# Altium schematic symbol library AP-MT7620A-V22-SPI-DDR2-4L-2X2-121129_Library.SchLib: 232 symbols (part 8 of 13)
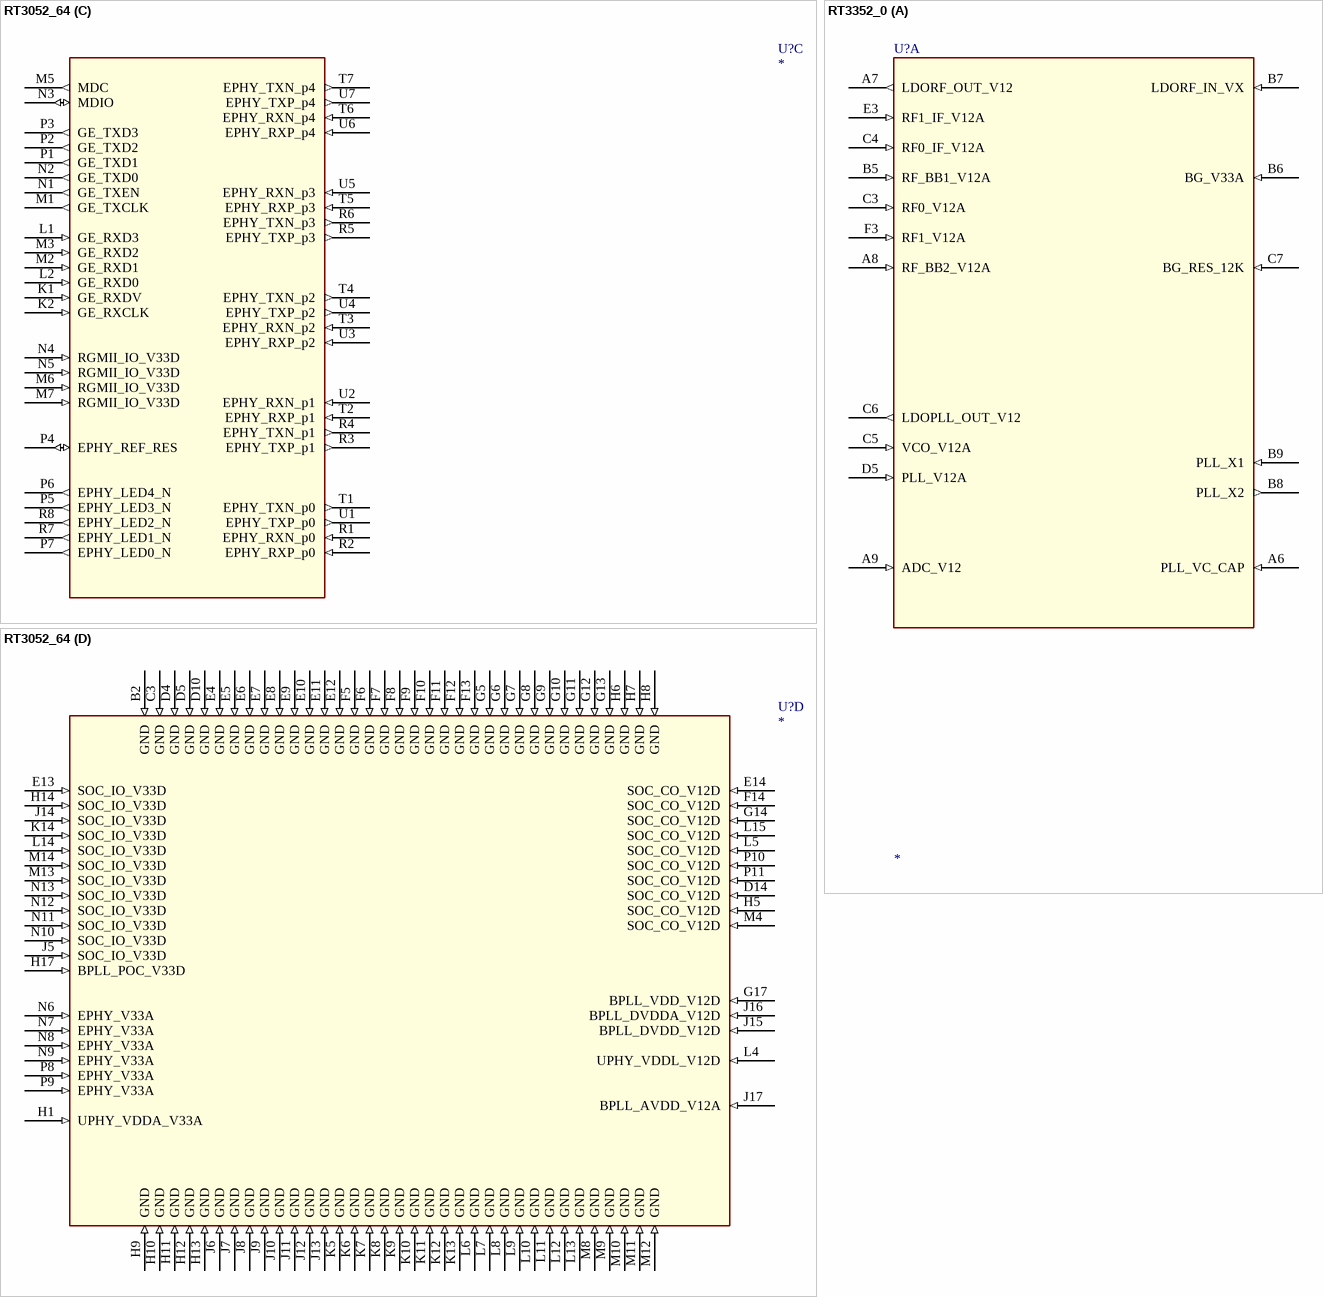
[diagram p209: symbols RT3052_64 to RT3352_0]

## RT3052_64
designator U?
footprint TFBGA289
part A pins: A1 RF0_V12A (in), A2 RF0_2G_OUT (out), A3 RF0_2G_INN (in), A4 RF0_2G_INP (in), A5 PLL_VC_CAP (in), A6 BG_RES_12K (in), A7 LDORF_OUT_V12 (out), A8 RF_BB2_V12A (in), A9 ADC_VREFN (in), A10 ADC_VREFP (in), A11 ADC_VREF025P (in), A12 ADC_VREF (in), A13 LDODIG_OUT_V12 (out), B1 RF1_2G_INP (in), B3 RF_BB1_V12A (in), B4 VCO_VCO_V12A (in), B5 PLL_DIV_V12A (in), B6 LDOPLL_OUT_V12 (out), B7 LDORF_IN_VX (in), B8 RF0_TSSI_IN (in), B9 ADC_V12A (in), B10 ADC_V12D (in), B11 ADC_VREF025N (in), B12 RF1_LNA_PE (out), C1 RF1_2G_INN (in), C2 RF1_V12A (in), C4 VCO_LO_V12A (in), C5 PLL_PRE_V12A (in), C6 PLL_X1 (io), C7 PLL_X2 (io), C8 BASE_TRX_IP (in), C9 BASE_TRX_QN (io), C10 RF0_LNA_PE (out), C11 LDOADC_IN_VX (in), C12 LDODIG_IN_VX (in), D1 RF1_2G_OUT (out), D2 RF0_PA_PE (out), D3 RF0_LO_V12A (in), D6 BG_V33A (in), D7 RF1_TSSI_IN (in), D8 BASE_TRX_IN (in), D9 BASE_TRX_QP (in), D11 LDOADC_OUT_V12 (in), D12 LDO_V33A (in), E1 RF1_PA_PE (out), E2 RF_V33A (in), E3 RF1_LO_V12A (in), F3 ANT_TRN (out), F4 WLAN_LED_N (out), G4 ANT_TRNB (out)
part B pins: A14 SRAM_CS_N (out), A15 MA20 (io), A16 MD1 (io), A17 MD6 (io), B13 OE_N (out), B14 FLASH_CS_N (out), B15 MD0 (io), B16 MD5 (io), B17 MD4 (io), C13 WE_N (out), C14 MA21 (io), C15 MD3 (io), C16 MD8 (io), C17 MD9 (io), D13 MA22 (io), D15 MD2 (io), D16 MD10 (io), D17 MD13 (io), E15 MD7 (io), E16 MD14 (io), E17 MD15 (io), F1 DSR_N (in), F2 TXD (out), F15 MD11 (io), F16 MA3 (io), F17 MA2 (io), G1 CTS_N (in), G2 RTS_N (out), G3 TXD2 (out), G15 MD12 (io), G16 MA1 (io), H2 UPHY_VRES (io), H3 DCD_N (in), H4 RXD2 (in), H15 MA4 (io), H16 MA0 (io), J1 UPHY_PADP (io), J2 UPHY_PADM (io), J3 RXD (in), J4 DTR_N (out), K3 UPHY_VBUS (io), K4 RIN (in), K15 MA5 (io), K16 MA7 (io), K17 MA6 (io), L3 UPHY_ID (io), L16 MA9 (io), L17 MA8 (io), M15 MA15 (io), M16 MA11 (io), M17 MA10 (io), N14 MD26 (io), N15 MA19 (io), N16 MA13 (io), N17 MA14 (io), P12 MD31 (io), P13 MD27 (io), P14 MD21 (io), P15 MD18 (io), P16 MA18 (io), P17 MA12 (io), R9 SPI_DIN (in), R10 I2C_SCLK (out), R11 JTAG_TDO (out), R12 MD25 (io), R13 MD30 (io), R14 MD22 (io), R15 MD19 (io), R16 SDRAM_CLK (out), R17 MA17 (io), T8 PORST_N (in), T9 SPI_CLK (out), T10 I2C_SD (io), T11 JTAG_TDI (in), T12 JTAG_TRST_N (in), T13 MD28 (io), T14 MD20 (io), T15 MD16 (io), T16 SDRAM_RAS_N (out), T17 MA16 (io), U8 SPI_DOUT (out), U9 SPI_EN (out), U10 GPIO0 (io), U11 JTAG_TMS (in), U12 JTAG_TCLK (in), U13 MD29 (io), U14 MD24 (io), U15 MD23 (io), U16 MD17 (io), U17 SDRAM_CS_N (out)
part C pins: K1 GE_RXDV (in), K2 GE_RXCLK (in), L1 GE_RXD3 (in), L2 GE_RXD0 (in), M1 GE_TXCLK (out), M2 GE_RXD1 (in), M3 GE_RXD2 (in), M5 MDC (out), M6 RGMII_IO_V33D (in), M7 RGMII_IO_V33D (in), N1 GE_TXEN (out), N2 GE_TXD0 (out), N3 MDIO (io), N4 RGMII_IO_V33D (in), N5 RGMII_IO_V33D (in), P1 GE_TXD1 (out), P2 GE_TXD2 (out), P3 GE_TXD3 (out), P4 EPHY_REF_RES (io), P5 EPHY_LED3_N (out), P6 EPHY_LED4_N (out), P7 EPHY_LED0_N (out), R1 EPHY_RXN_p0 (in), R2 EPHY_RXP_p0 (in), R3 EPHY_TXP_p1 (out), R4 EPHY_TXN_p1 (out), R5 EPHY_TXP_p3 (out), R6 EPHY_TXN_p3 (out), R7 EPHY_LED1_N (out), R8 EPHY_LED2_N (out), T1 EPHY_TXN_p0 (out), T2 EPHY_RXP_p1 (in), T3 EPHY_RXN_p2 (in), T4 EPHY_TXN_p2 (out), T5 EPHY_RXP_p3 (in), T6 EPHY_RXN_p4 (in), T7 EPHY_TXN_p4 (out), U1 EPHY_TXP_p0 (out), U2 EPHY_RXN_p1 (in), U3 EPHY_RXP_p2 (in), U4 EPHY_TXP_p2 (out), U5 EPHY_RXN_p3 (in), U6 EPHY_RXP_p4 (in), U7 EPHY_TXP_p4 (out)
part D pins: B2 GND (in), C3 GND (in), D4 GND (in), D5 GND (in), D10 GND (in), D14 SOC_CO_V12D (in), E4 GND (in), E5 GND (in), E6 GND (in), E7 GND (in), E8 GND (in), E9 GND (in), E10 GND (in), E11 GND (in), E12 GND (in), E13 SOC_IO_V33D (in), E14 SOC_CO_V12D (in), F5 GND (in), F6 GND (in), F7 GND (in), F8 GND (in), F9 GND (in), F10 GND (in), F11 GND (in), F12 GND (in), F13 GND (in), F14 SOC_CO_V12D (in), G5 GND (in), G6 GND (in), G7 GND (in), G8 GND (in), G9 GND (in), G10 GND (in), G11 GND (in), G12 GND (in), G13 GND (in), G14 SOC_CO_V12D (in), G17 BPLL_VDD_V12D (in), H1 UPHY_VDDA_V33A (in), H5 SOC_CO_V12D (in), H6 GND (in), H7 GND (in), H8 GND (in), H9 GND (in), H10 GND (in), H11 GND (in), H12 GND (in), H13 GND (in), H14 SOC_IO_V33D (in), H17 BPLL_POC_V33D (in), J5 SOC_IO_V33D (in), J6 GND (in), J7 GND (in), J8 GND (in), J9 GND (in), J10 GND (in), J11 GND (in), J12 GND (in), J13 GND (in), J14 SOC_IO_V33D (in), J15 BPLL_DVDD_V12D (in), J16 BPLL_DVDDA_V12D (in), J17 BPLL_AVDD_V12A (in), K5 GND (in), K6 GND (in), K7 GND (in), K8 GND (in), K9 GND (in), K10 GND (in), K11 GND (in), K12 GND (in), K13 GND (in), K14 SOC_IO_V33D (in), L4 UPHY_VDDL_V12D (in), L5 SOC_CO_V12D (in), L6 GND (in), L7 GND (in), L8 GND (in), L9 GND (in), L10 GND (in), L11 GND (in), L12 GND (in), L13 GND (in), L14 SOC_IO_V33D (in), L15 SOC_CO_V12D (in), M4 SOC_CO_V12D (in), M8 GND (in), M9 GND (in), M10 GND (in), M11 GND (in), M12 GND (in), M13 SOC_IO_V33D (in), M14 SOC_IO_V33D (in), N6 EPHY_V33A (in), N7 EPHY_V33A (in), N8 EPHY_V33A (in), N9 EPHY_V33A (in), N10 SOC_IO_V33D (in), N11 SOC_IO_V33D (in), N12 SOC_IO_V33D (in), N13 SOC_IO_V33D (in), P8 EPHY_V33A (in), P9 EPHY_V33A (in), P10 SOC_CO_V12D (in), P11 SOC_CO_V12D (in)

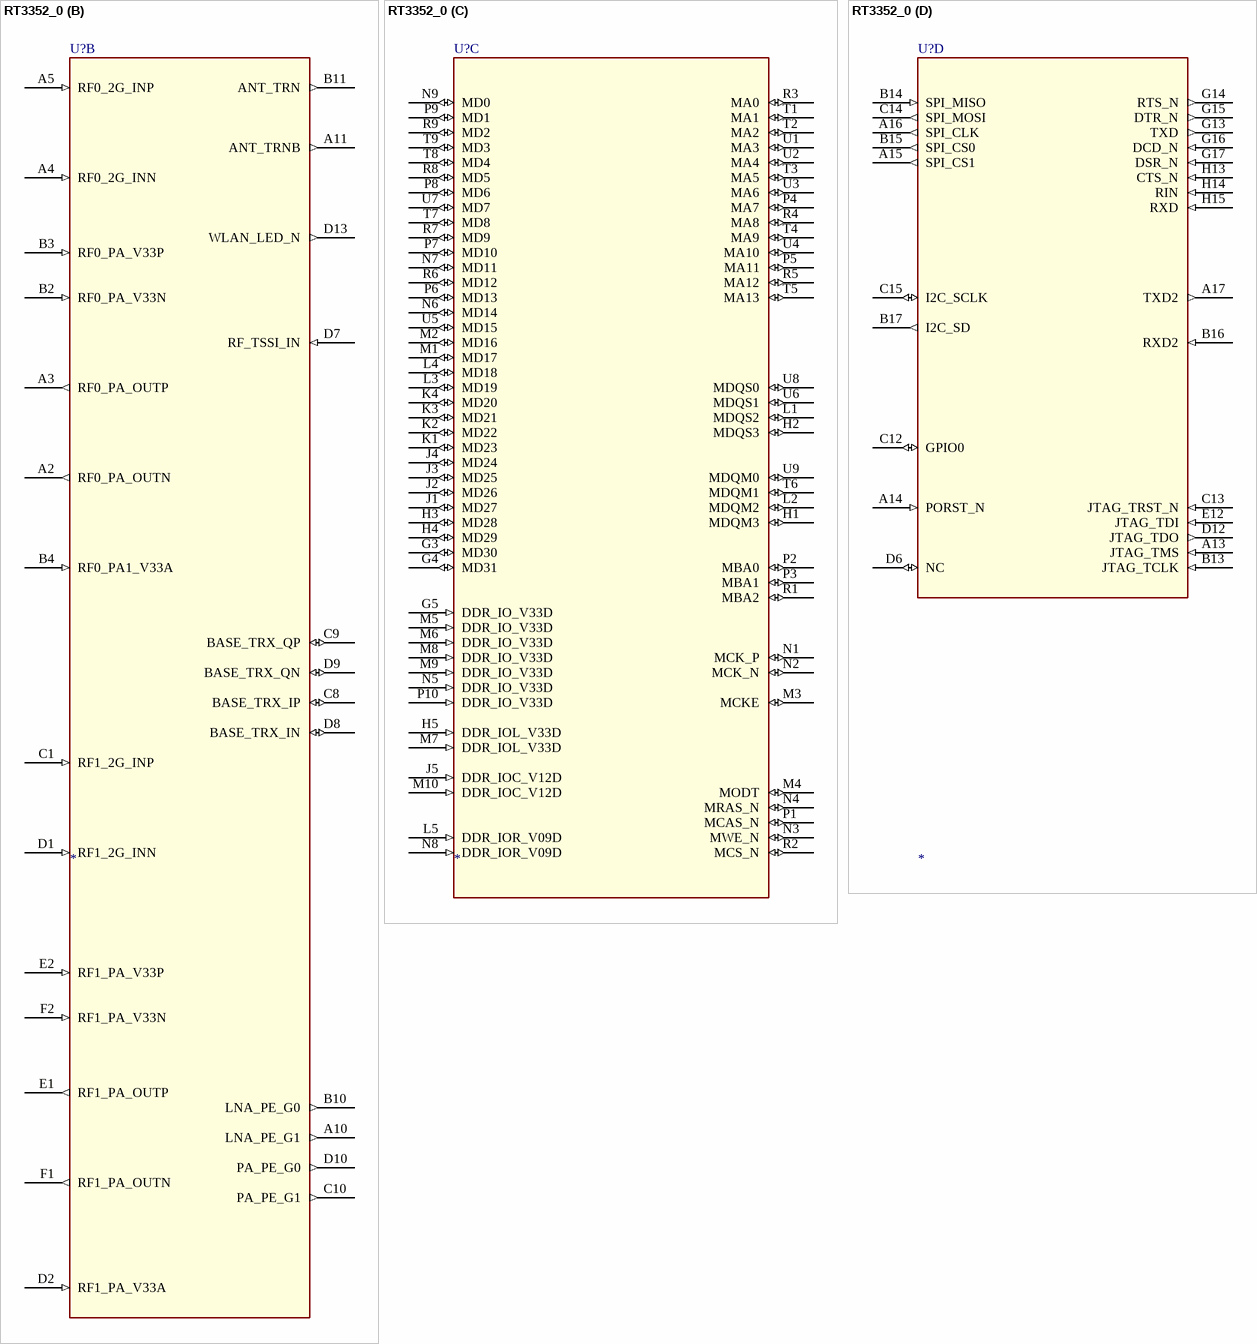
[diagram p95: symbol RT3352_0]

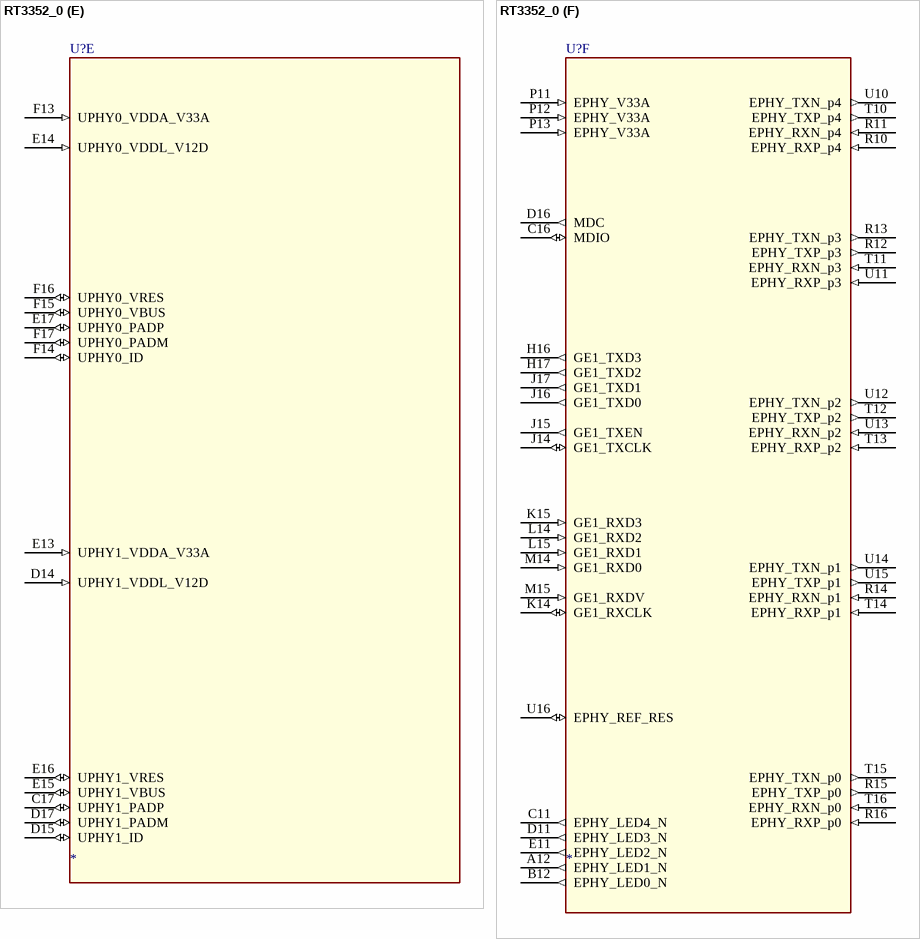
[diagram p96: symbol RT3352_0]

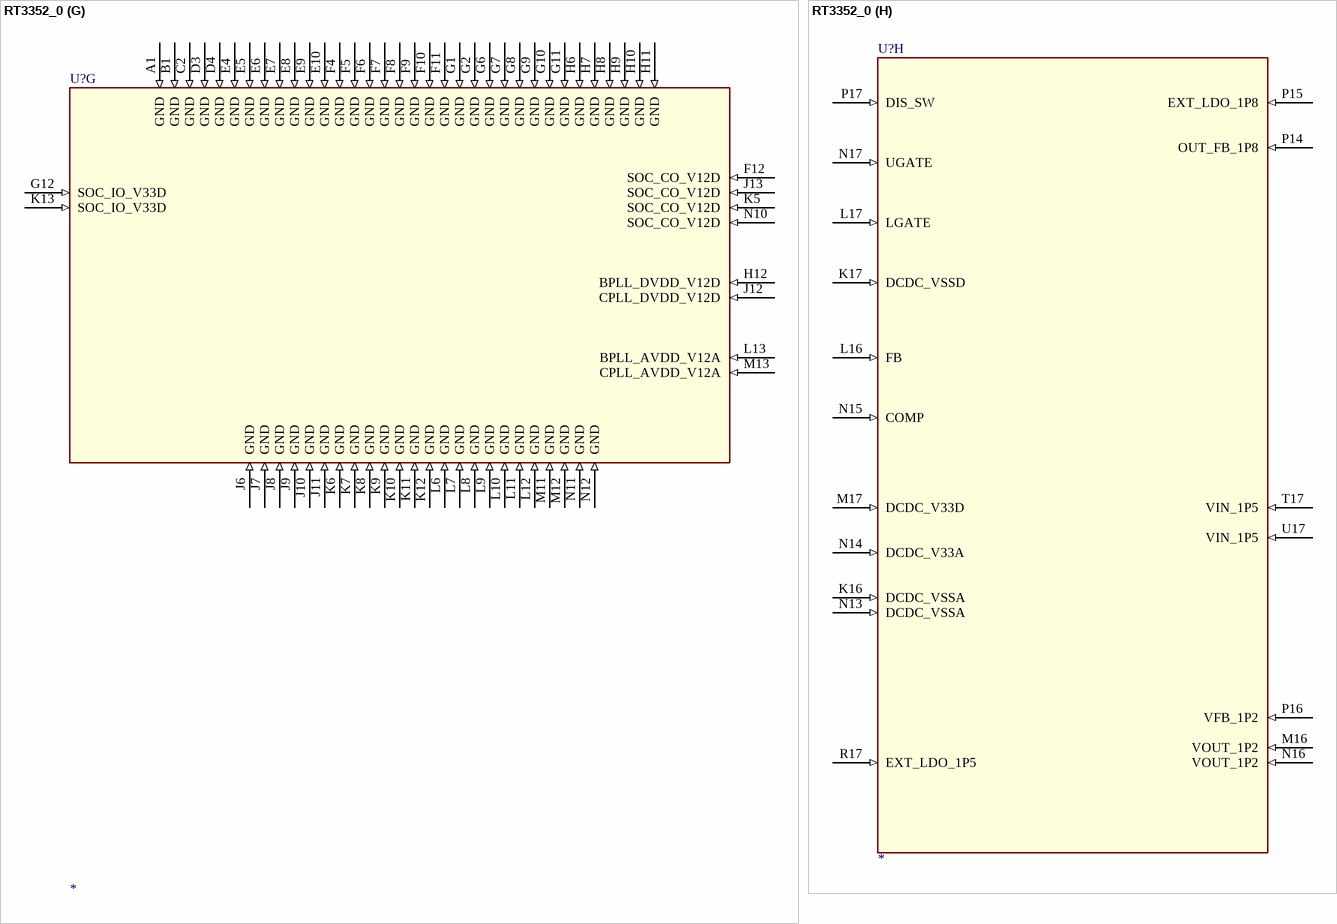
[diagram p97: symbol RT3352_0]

## RT3352_0
designator U?
part A pins: A6 PLL_VC_CAP (in), A7 LDORF_OUT_V12 (out), A8 RF_BB2_V12A (in), A9 ADC_V12 (in), B5 RF_BB1_V12A (in), B6 BG_V33A (in), B7 LDORF_IN_VX (in), B8 PLL_X2 (out), B9 PLL_X1 (in), C3 RF0_V12A (in), C4 RF0_IF_V12A (in), C5 VCO_V12A (in), C6 LDOPLL_OUT_V12 (out), C7 BG_RES_12K (in), D5 PLL_V12A (in), E3 RF1_IF_V12A (in), F3 RF1_V12A (in)
part B pins: A2 RF0_PA_OUTN (out), A3 RF0_PA_OUTP (out), A4 RF0_2G_INN (in), A5 RF0_2G_INP (in), A10 LNA_PE_G1 (out), A11 ANT_TRNB (out), B2 RF0_PA_V33N (in), B3 RF0_PA_V33P (in), B4 RF0_PA1_V33A (in), B10 LNA_PE_G0 (out), B11 ANT_TRN (out), C1 RF1_2G_INP (in), C8 BASE_TRX_IP (io), C9 BASE_TRX_QP (io), C10 PA_PE_G1 (out), D1 RF1_2G_INN (in), D2 RF1_PA_V33A (in), D7 RF_TSSI_IN (in), D8 BASE_TRX_IN (io), D9 BASE_TRX_QN (io), D10 PA_PE_G0 (out), D13 WLAN_LED_N (out), E1 RF1_PA_OUTP (out), E2 RF1_PA_V33P (in), F1 RF1_PA_OUTN (out), F2 RF1_PA_V33N (in)
part C pins: G3 MD30 (io), G4 MD31 (io), G5 DDR_IO_V33D (in), H1 MDQM3 (io), H2 MDQS3 (io), H3 MD28 (io), H4 MD29 (io), H5 DDR_IOL_V33D (in), J1 MD27 (io), J2 MD26 (io), J3 MD25 (io), J4 MD24 (io), J5 DDR_IOC_V12D (in), K1 MD23 (io), K2 MD22 (io), K3 MD21 (io), K4 MD20 (io), L1 MDQS2 (io), L2 MDQM2 (io), L3 MD19 (io), L4 MD18 (io), L5 DDR_IOR_V09D (in), M1 MD17 (io), M2 MD16 (io), M3 MCKE (io), M4 MODT (io), M5 DDR_IO_V33D (in), M6 DDR_IO_V33D (in), M7 DDR_IOL_V33D (in), M8 DDR_IO_V33D (in), M9 DDR_IO_V33D (in), M10 DDR_IOC_V12D (in), N1 MCK_P (io), N2 MCK_N (io), N3 MWE_N (io), N4 MRAS_N (io), N5 DDR_IO_V33D (in), N6 MD14 (io), N7 MD11 (io), N8 DDR_IOR_V09D (in), N9 MD0 (io), P1 MCAS_N (io), P2 MBA0 (io), P3 MBA1 (io), P4 MA7 (io), P5 MA11 (io), P6 MD13 (io), P7 MD10 (io), P8 MD6 (io), P9 MD1 (io), P10 DDR_IO_V33D (in), R1 MBA2 (io), R2 MCS_N (io), R3 MA0 (io), R4 MA8 (io), R5 MA12 (io), R6 MD12 (io), R7 MD9 (io), R8 MD5 (io), R9 MD2 (io), T1 MA1 (io), T2 MA2 (io), T3 MA5 (io), T4 MA9 (io), T5 MA13 (io), T6 MDQM1 (io), T7 MD8 (io), T8 MD4 (io), T9 MD3 (io), U1 MA3 (io), U2 MA4 (io), U3 MA6 (io), U4 MA10 (io), U5 MD15 (io), U6 MDQS1 (io), U7 MD7 (io), U8 MDQS0 (io), U9 MDQM0 (io)
part D pins: A13 JTAG_TMS (in), A14 PORST_N (in), A15 SPI_CS1 (out), A16 SPI_CLK (out), A17 TXD2 (out), B13 JTAG_TCLK (in), B14 SPI_MISO (in), B15 SPI_CS0 (out), B16 RXD2 (in), B17 I2C_SD (out), C12 GPIO0 (io), C13 JTAG_TRST_N (in), C14 SPI_MOSI (out), C15 I2C_SCLK (io), D6 NC (io), D12 JTAG_TDO (out), E12 JTAG_TDI (in), G13 TXD (out), G14 RTS_N (out), G15 DTR_N (out), G16 DCD_N (in), G17 DSR_N (in), H13 CTS_N (in), H14 RIN (in), H15 RXD (in)
part E pins: C17 UPHY1_PADP (io), D14 UPHY1_VDDL_V12D (in), D15 UPHY1_ID (io), D17 UPHY1_PADM (io), E13 UPHY1_VDDA_V33A (in), E14 UPHY0_VDDL_V12D (in), E15 UPHY1_VBUS (io), E16 UPHY1_VRES (io), E17 UPHY0_PADP (io), F13 UPHY0_VDDA_V33A (in), F14 UPHY0_ID (io), F15 UPHY0_VBUS (io), F16 UPHY0_VRES (io), F17 UPHY0_PADM (io)
part F pins: A12 EPHY_LED1_N (out), B12 EPHY_LED0_N (out), C11 EPHY_LED4_N (out), C16 MDIO (io), D11 EPHY_LED3_N (out), D16 MDC (out), E11 EPHY_LED2_N (out), H16 GE1_TXD3 (out), H17 GE1_TXD2 (out), J14 GE1_TXCLK (io), J15 GE1_TXEN (out), J16 GE1_TXD0 (out), J17 GE1_TXD1 (out), K14 GE1_RXCLK (io), K15 GE1_RXD3 (in), L14 GE1_RXD2 (in), L15 GE1_RXD1 (in), M14 GE1_RXD0 (in), M15 GE1_RXDV (in), P11 EPHY_V33A (in), P12 EPHY_V33A (in), P13 EPHY_V33A (in), R10 EPHY_RXP_p4 (in), R11 EPHY_RXN_p4 (in), R12 EPHY_TXP_p3 (out), R13 EPHY_TXN_p3 (out), R14 EPHY_RXN_p1 (in), R15 EPHY_TXP_p0 (out), R16 EPHY_RXP_p0 (in), T10 EPHY_TXP_p4 (out), T11 EPHY_RXN_p3 (in), T12 EPHY_TXP_p2 (out), T13 EPHY_RXP_p2 (in), T14 EPHY_RXP_p1 (in), T15 EPHY_TXN_p0 (out), T16 EPHY_RXN_p0 (in), U10 EPHY_TXN_p4 (out), U11 EPHY_RXP_p3 (in), U12 EPHY_TXN_p2 (out), U13 EPHY_RXN_p2 (in), U14 EPHY_TXN_p1 (out), U15 EPHY_TXP_p1 (out), U16 EPHY_REF_RES (io)
part G pins: A1 GND (in), B1 GND (in), C2 GND (in), D3 GND (in), D4 GND (in), E4 GND (in), E5 GND (in), E6 GND (in), E7 GND (in), E8 GND (in), E9 GND (in), E10 GND (in), F4 GND (in), F5 GND (in), F6 GND (in), F7 GND (in), F8 GND (in), F9 GND (in), F10 GND (in), F11 GND (in), F12 SOC_CO_V12D (in), G1 GND (in), G2 GND (in), G6 GND (in), G7 GND (in), G8 GND (in), G9 GND (in), G10 GND (in), G11 GND (in), G12 SOC_IO_V33D (in), H6 GND (in), H7 GND (in), H8 GND (in), H9 GND (in), H10 GND (in), H11 GND (in), H12 BPLL_DVDD_V12D (in), J6 GND (in), J7 GND (in), J8 GND (in), J9 GND (in), J10 GND (in), J11 GND (in), J12 CPLL_DVDD_V12D (in), J13 SOC_CO_V12D (in), K5 SOC_CO_V12D (in), K6 GND (in), K7 GND (in), K8 GND (in), K9 GND (in), K10 GND (in), K11 GND (in), K12 GND (in), K13 SOC_IO_V33D (in), L6 GND (in), L7 GND (in), L8 GND (in), L9 GND (in), L10 GND (in), L11 GND (in), L12 GND (in), L13 BPLL_AVDD_V12A (in), M11 GND (in), M12 GND (in), M13 CPLL_AVDD_V12A (in), N10 SOC_CO_V12D (in), N11 GND (in), N12 GND (in)
part H pins: K16 DCDC_VSSA (in), K17 DCDC_VSSD (in), L16 FB (in), L17 LGATE (in), M16 VOUT_1P2 (in), M17 DCDC_V33D (in), N13 DCDC_VSSA (in), N14 DCDC_V33A (in), N15 COMP (in), N16 VOUT_1P2 (in), N17 UGATE (in), P14 OUT_FB_1P8 (in), P15 EXT_LDO_1P8 (in), P16 VFB_1P2 (in), P17 DIS_SW (in), R17 EXT_LDO_1P5 (in), T17 VIN_1P5 (in), U17 VIN_1P5 (in)

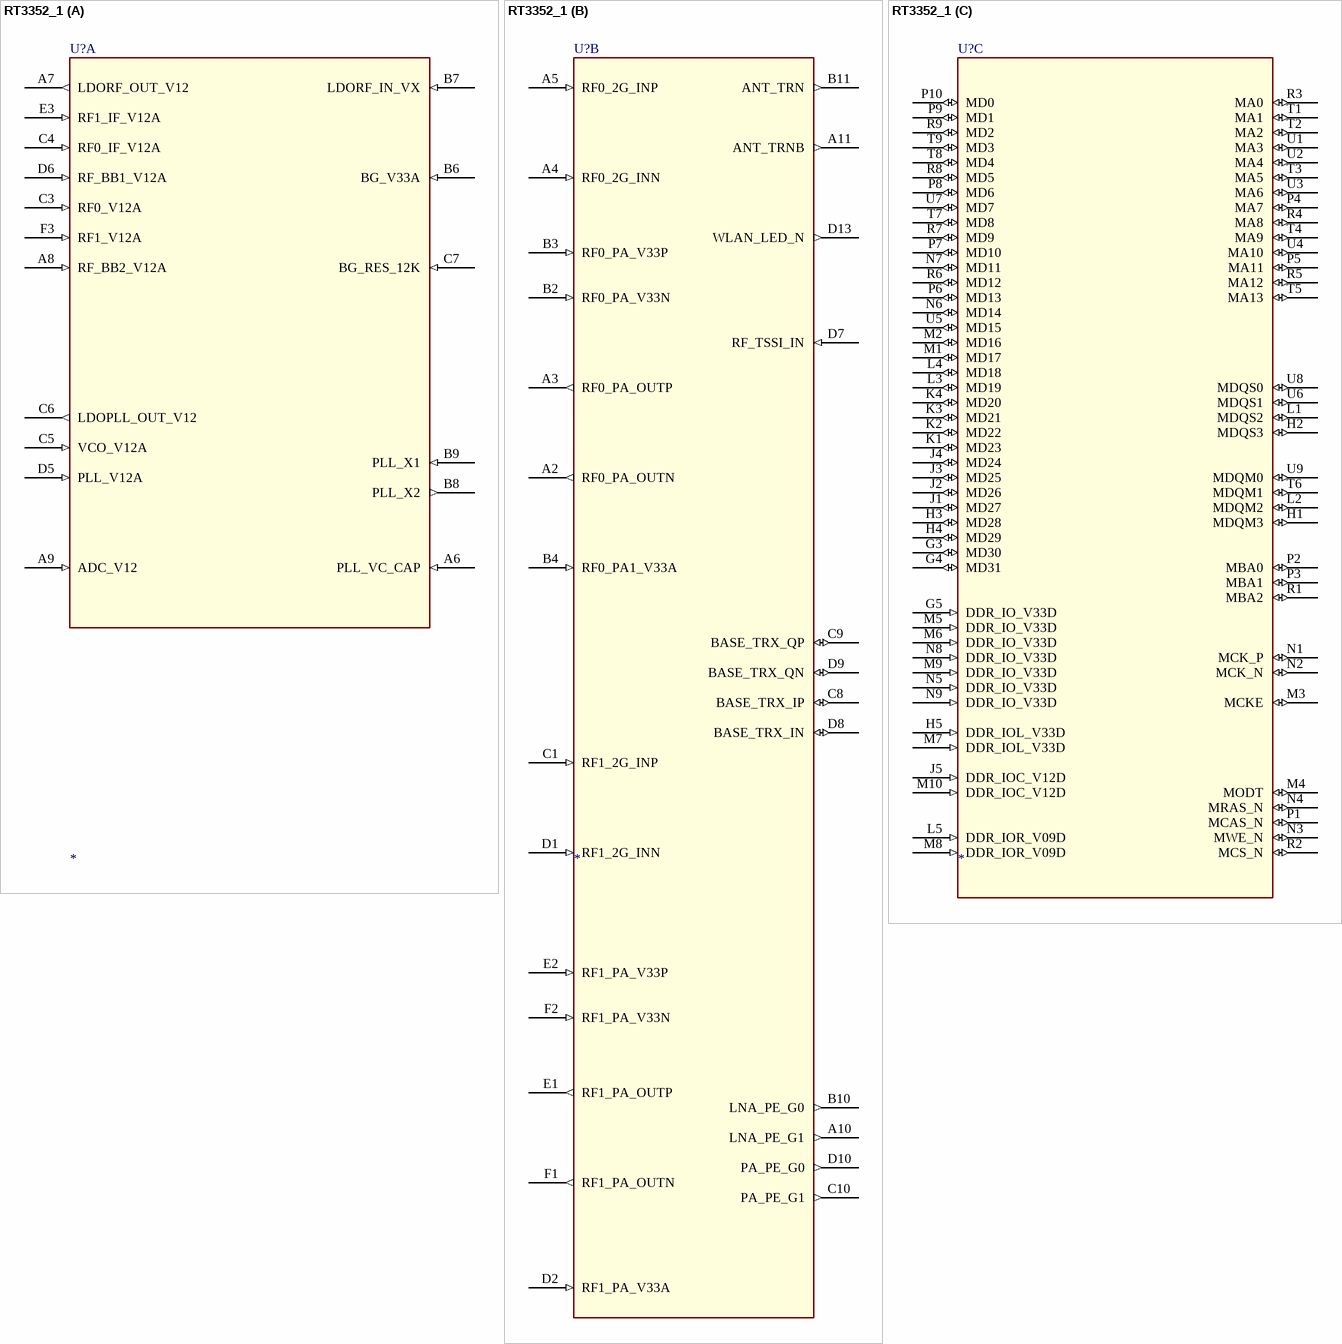
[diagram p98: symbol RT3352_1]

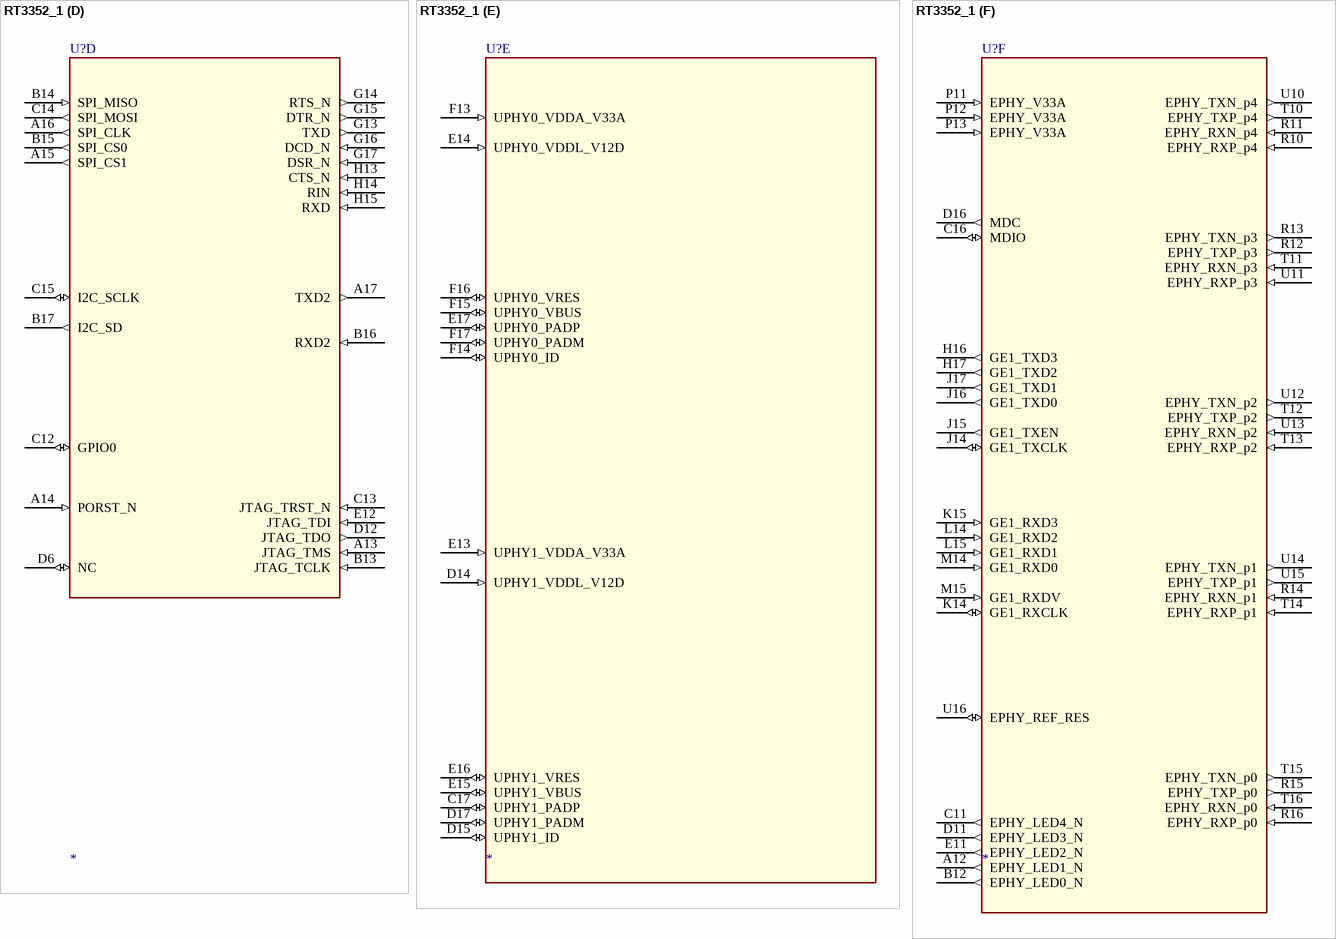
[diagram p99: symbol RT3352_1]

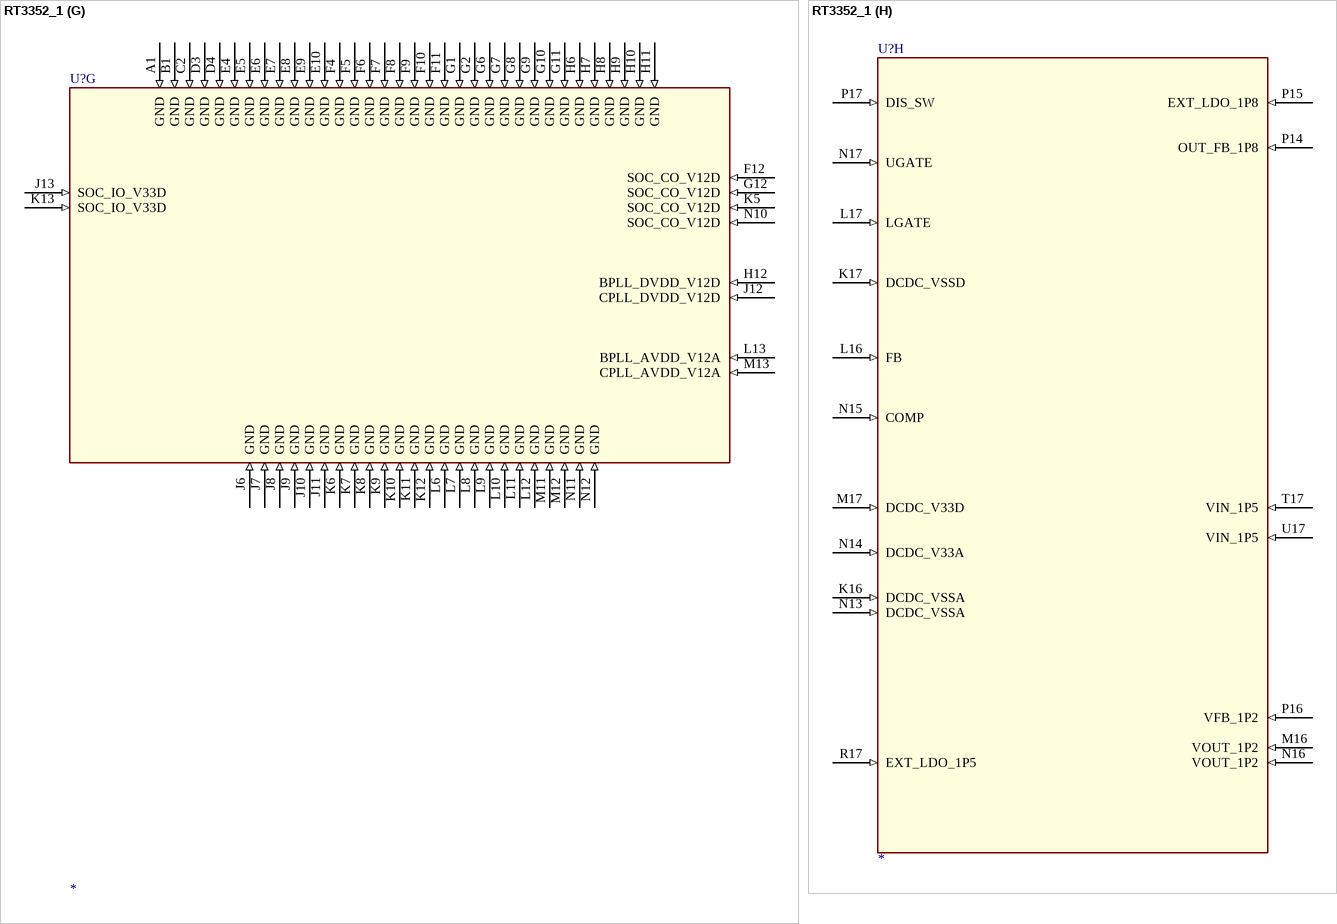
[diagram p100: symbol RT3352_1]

## RT3352_1
designator U?
part A pins: A6 PLL_VC_CAP (in), A7 LDORF_OUT_V12 (out), A8 RF_BB2_V12A (in), A9 ADC_V12 (in), B6 BG_V33A (in), B7 LDORF_IN_VX (in), B8 PLL_X2 (out), B9 PLL_X1 (in), C3 RF0_V12A (in), C4 RF0_IF_V12A (in), C5 VCO_V12A (in), C6 LDOPLL_OUT_V12 (out), C7 BG_RES_12K (in), D5 PLL_V12A (in), D6 RF_BB1_V12A (in), E3 RF1_IF_V12A (in), F3 RF1_V12A (in)
part B pins: A2 RF0_PA_OUTN (out), A3 RF0_PA_OUTP (out), A4 RF0_2G_INN (in), A5 RF0_2G_INP (in), A10 LNA_PE_G1 (out), A11 ANT_TRNB (out), B2 RF0_PA_V33N (in), B3 RF0_PA_V33P (in), B4 RF0_PA1_V33A (in), B10 LNA_PE_G0 (out), B11 ANT_TRN (out), C1 RF1_2G_INP (in), C8 BASE_TRX_IP (io), C9 BASE_TRX_QP (io), C10 PA_PE_G1 (out), D1 RF1_2G_INN (in), D2 RF1_PA_V33A (in), D7 RF_TSSI_IN (in), D8 BASE_TRX_IN (io), D9 BASE_TRX_QN (io), D10 PA_PE_G0 (out), D13 WLAN_LED_N (out), E1 RF1_PA_OUTP (out), E2 RF1_PA_V33P (in), F1 RF1_PA_OUTN (out), F2 RF1_PA_V33N (in)
part C pins: G3 MD30 (io), G4 MD31 (io), G5 DDR_IO_V33D (in), H1 MDQM3 (io), H2 MDQS3 (io), H3 MD28 (io), H4 MD29 (io), H5 DDR_IOL_V33D (in), J1 MD27 (io), J2 MD26 (io), J3 MD25 (io), J4 MD24 (io), J5 DDR_IOC_V12D (in), K1 MD23 (io), K2 MD22 (io), K3 MD21 (io), K4 MD20 (io), L1 MDQS2 (io), L2 MDQM2 (io), L3 MD19 (io), L4 MD18 (io), L5 DDR_IOR_V09D (in), M1 MD17 (io), M2 MD16 (io), M3 MCKE (io), M4 MODT (io), M5 DDR_IO_V33D (in), M6 DDR_IO_V33D (in), M7 DDR_IOL_V33D (in), M8 DDR_IOR_V09D (in), M9 DDR_IO_V33D (in), M10 DDR_IOC_V12D (in), N1 MCK_P (io), N2 MCK_N (io), N3 MWE_N (io), N4 MRAS_N (io), N5 DDR_IO_V33D (in), N6 MD14 (io), N7 MD11 (io), N8 DDR_IO_V33D (in), N9 DDR_IO_V33D (in), P1 MCAS_N (io), P2 MBA0 (io), P3 MBA1 (io), P4 MA7 (io), P5 MA11 (io), P6 MD13 (io), P7 MD10 (io), P8 MD6 (io), P9 MD1 (io), P10 MD0 (io), R1 MBA2 (io), R2 MCS_N (io), R3 MA0 (io), R4 MA8 (io), R5 MA12 (io), R6 MD12 (io), R7 MD9 (io), R8 MD5 (io), R9 MD2 (io), T1 MA1 (io), T2 MA2 (io), T3 MA5 (io), T4 MA9 (io), T5 MA13 (io), T6 MDQM1 (io), T7 MD8 (io), T8 MD4 (io), T9 MD3 (io), U1 MA3 (io), U2 MA4 (io), U3 MA6 (io), U4 MA10 (io), U5 MD15 (io), U6 MDQS1 (io), U7 MD7 (io), U8 MDQS0 (io), U9 MDQM0 (io)
part D pins: A13 JTAG_TMS (in), A14 PORST_N (in), A15 SPI_CS1 (out), A16 SPI_CLK (out), A17 TXD2 (out), B13 JTAG_TCLK (in), B14 SPI_MISO (in), B15 SPI_CS0 (out), B16 RXD2 (in), B17 I2C_SD (out), C12 GPIO0 (io), C13 JTAG_TRST_N (in), C14 SPI_MOSI (out), C15 I2C_SCLK (io), D6 NC (io), D12 JTAG_TDO (out), E12 JTAG_TDI (in), G13 TXD (out), G14 RTS_N (out), G15 DTR_N (out), G16 DCD_N (in), G17 DSR_N (in), H13 CTS_N (in), H14 RIN (in), H15 RXD (in)
part E pins: C17 UPHY1_PADP (io), D14 UPHY1_VDDL_V12D (in), D15 UPHY1_ID (io), D17 UPHY1_PADM (io), E13 UPHY1_VDDA_V33A (in), E14 UPHY0_VDDL_V12D (in), E15 UPHY1_VBUS (io), E16 UPHY1_VRES (io), E17 UPHY0_PADP (io), F13 UPHY0_VDDA_V33A (in), F14 UPHY0_ID (io), F15 UPHY0_VBUS (io), F16 UPHY0_VRES (io), F17 UPHY0_PADM (io)
part F pins: A12 EPHY_LED1_N (out), B12 EPHY_LED0_N (out), C11 EPHY_LED4_N (out), C16 MDIO (io), D11 EPHY_LED3_N (out), D16 MDC (out), E11 EPHY_LED2_N (out), H16 GE1_TXD3 (out), H17 GE1_TXD2 (out), J14 GE1_TXCLK (io), J15 GE1_TXEN (out), J16 GE1_TXD0 (out), J17 GE1_TXD1 (out), K14 GE1_RXCLK (io), K15 GE1_RXD3 (in), L14 GE1_RXD2 (in), L15 GE1_RXD1 (in), M14 GE1_RXD0 (in), M15 GE1_RXDV (in), P11 EPHY_V33A (in), P12 EPHY_V33A (in), P13 EPHY_V33A (in), R10 EPHY_RXP_p4 (in), R11 EPHY_RXN_p4 (in), R12 EPHY_TXP_p3 (out), R13 EPHY_TXN_p3 (out), R14 EPHY_RXN_p1 (in), R15 EPHY_TXP_p0 (out), R16 EPHY_RXP_p0 (in), T10 EPHY_TXP_p4 (out), T11 EPHY_RXN_p3 (in), T12 EPHY_TXP_p2 (out), T13 EPHY_RXP_p2 (in), T14 EPHY_RXP_p1 (in), T15 EPHY_TXN_p0 (out), T16 EPHY_RXN_p0 (in), U10 EPHY_TXN_p4 (out), U11 EPHY_RXP_p3 (in), U12 EPHY_TXN_p2 (out), U13 EPHY_RXN_p2 (in), U14 EPHY_TXN_p1 (out), U15 EPHY_TXP_p1 (out), U16 EPHY_REF_RES (io)
part G pins: A1 GND (in), B1 GND (in), C2 GND (in), D3 GND (in), D4 GND (in), E4 GND (in), E5 GND (in), E6 GND (in), E7 GND (in), E8 GND (in), E9 GND (in), E10 GND (in), F4 GND (in), F5 GND (in), F6 GND (in), F7 GND (in), F8 GND (in), F9 GND (in), F10 GND (in), F11 GND (in), F12 SOC_CO_V12D (in), G1 GND (in), G2 GND (in), G6 GND (in), G7 GND (in), G8 GND (in), G9 GND (in), G10 GND (in), G11 GND (in), G12 SOC_CO_V12D (in), H6 GND (in), H7 GND (in), H8 GND (in), H9 GND (in), H10 GND (in), H11 GND (in), H12 BPLL_DVDD_V12D (in), J6 GND (in), J7 GND (in), J8 GND (in), J9 GND (in), J10 GND (in), J11 GND (in), J12 CPLL_DVDD_V12D (in), J13 SOC_IO_V33D (in), K5 SOC_CO_V12D (in), K6 GND (in), K7 GND (in), K8 GND (in), K9 GND (in), K10 GND (in), K11 GND (in), K12 GND (in), K13 SOC_IO_V33D (in), L6 GND (in), L7 GND (in), L8 GND (in), L9 GND (in), L10 GND (in), L11 GND (in), L12 GND (in), L13 BPLL_AVDD_V12A (in), M11 GND (in), M12 GND (in), M13 CPLL_AVDD_V12A (in), N10 SOC_CO_V12D (in), N11 GND (in), N12 GND (in)
part H pins: K16 DCDC_VSSA (in), K17 DCDC_VSSD (in), L16 FB (in), L17 LGATE (in), M16 VOUT_1P2 (in), M17 DCDC_V33D (in), N13 DCDC_VSSA (in), N14 DCDC_V33A (in), N15 COMP (in), N16 VOUT_1P2 (in), N17 UGATE (in), P14 OUT_FB_1P8 (in), P15 EXT_LDO_1P8 (in), P16 VFB_1P2 (in), P17 DIS_SW (in), R17 EXT_LDO_1P5 (in), T17 VIN_1P5 (in), U17 VIN_1P5 (in)

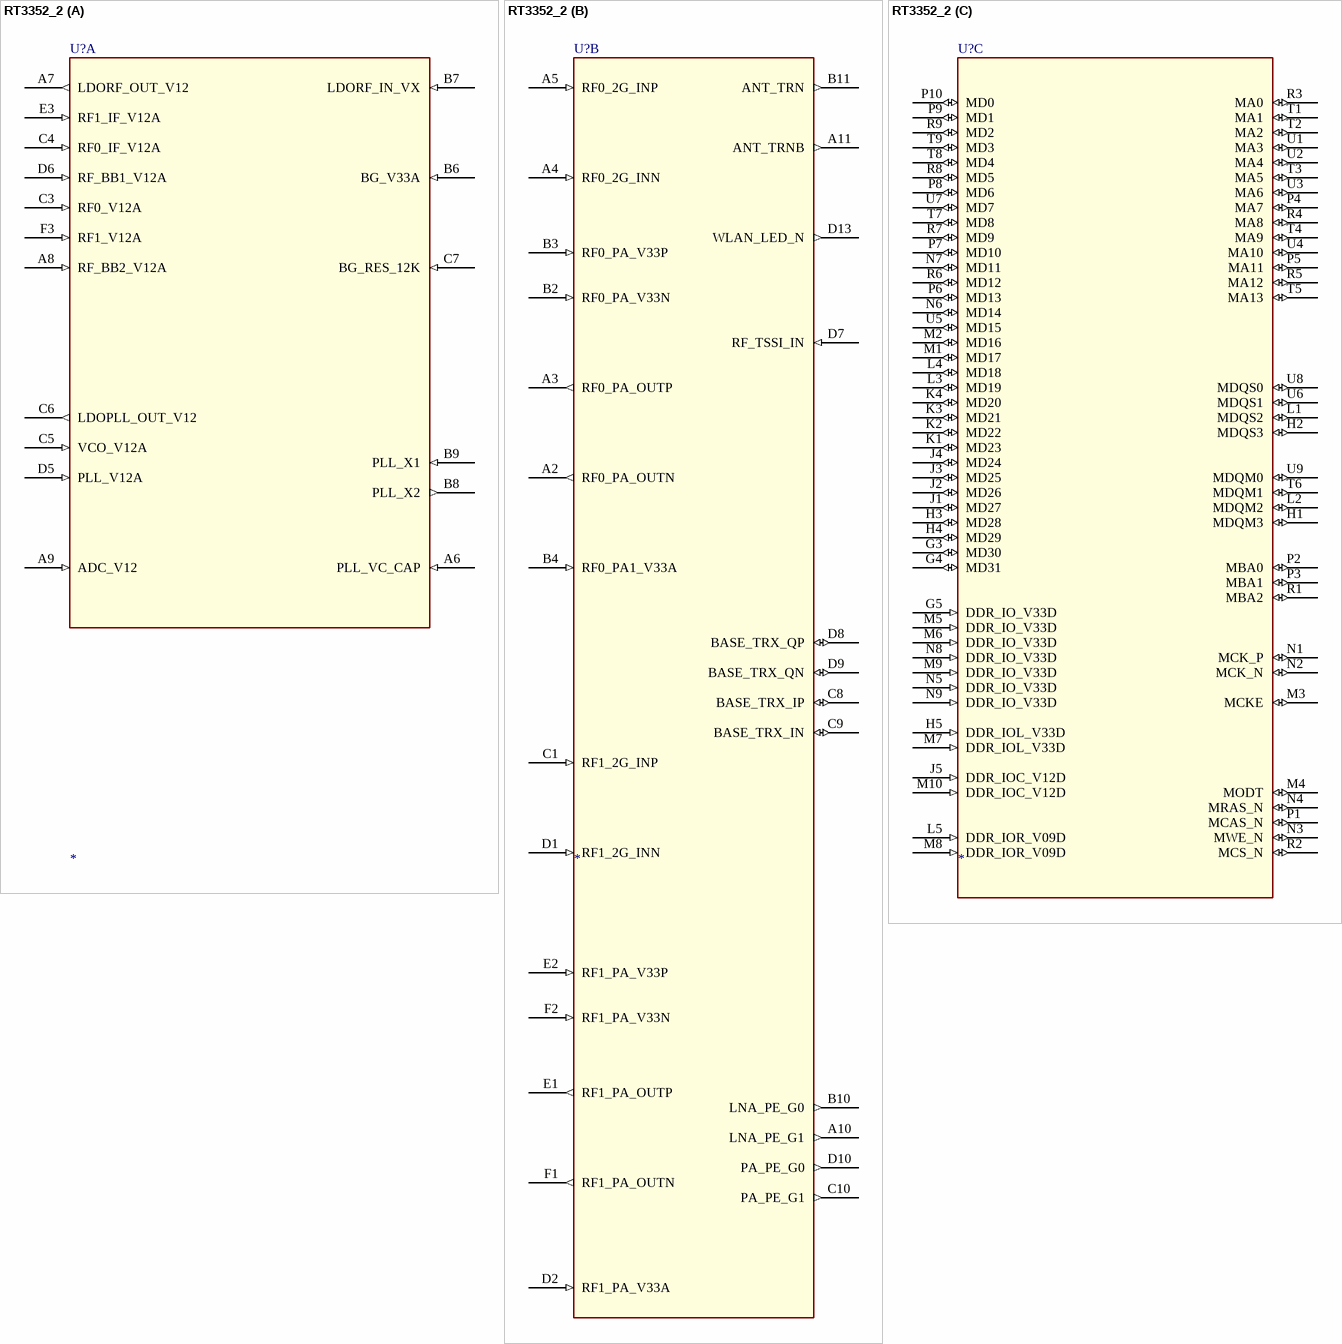
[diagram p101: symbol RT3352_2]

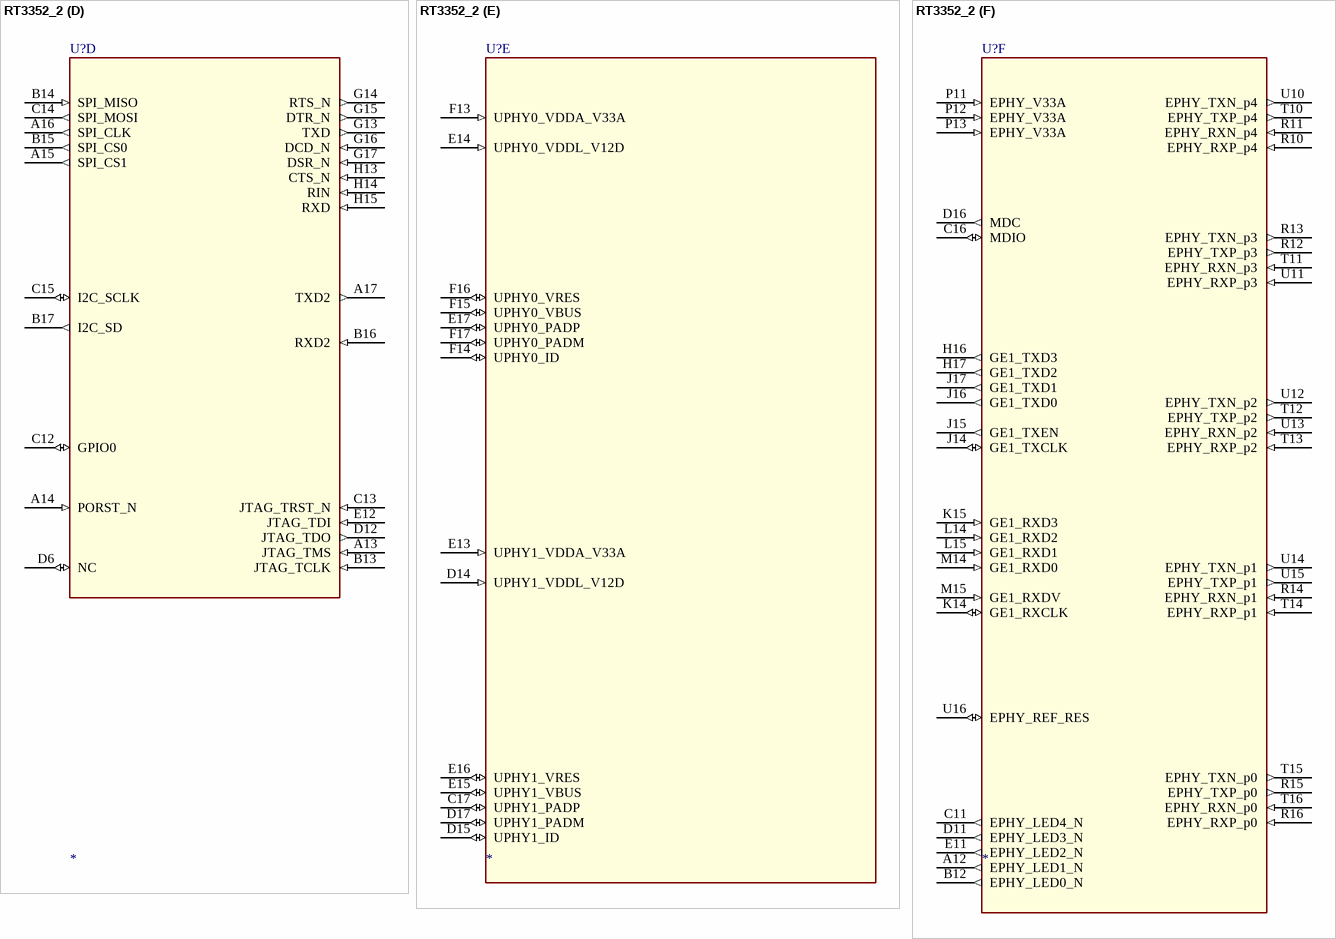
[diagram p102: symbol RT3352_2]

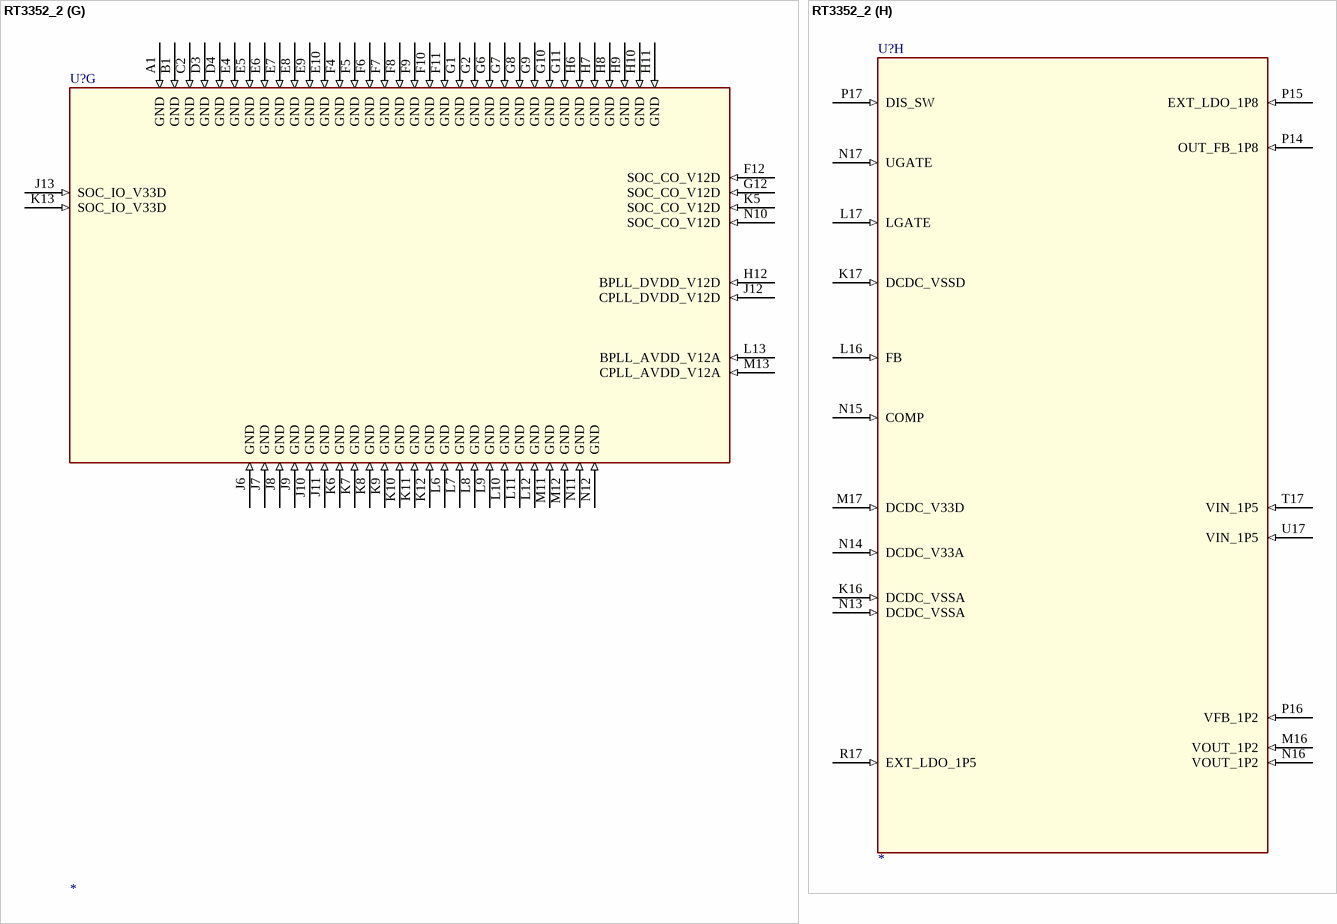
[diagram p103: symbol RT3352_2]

## RT3352_2
designator U?
part A pins: A6 PLL_VC_CAP (in), A7 LDORF_OUT_V12 (out), A8 RF_BB2_V12A (in), A9 ADC_V12 (in), B6 BG_V33A (in), B7 LDORF_IN_VX (in), B8 PLL_X2 (out), B9 PLL_X1 (in), C3 RF0_V12A (in), C4 RF0_IF_V12A (in), C5 VCO_V12A (in), C6 LDOPLL_OUT_V12 (out), C7 BG_RES_12K (in), D5 PLL_V12A (in), D6 RF_BB1_V12A (in), E3 RF1_IF_V12A (in), F3 RF1_V12A (in)
part B pins: A2 RF0_PA_OUTN (out), A3 RF0_PA_OUTP (out), A4 RF0_2G_INN (in), A5 RF0_2G_INP (in), A10 LNA_PE_G1 (out), A11 ANT_TRNB (out), B2 RF0_PA_V33N (in), B3 RF0_PA_V33P (in), B4 RF0_PA1_V33A (in), B10 LNA_PE_G0 (out), B11 ANT_TRN (out), C1 RF1_2G_INP (in), C8 BASE_TRX_IP (io), C9 BASE_TRX_IN (io), C10 PA_PE_G1 (out), D1 RF1_2G_INN (in), D2 RF1_PA_V33A (in), D7 RF_TSSI_IN (in), D8 BASE_TRX_QP (io), D9 BASE_TRX_QN (io), D10 PA_PE_G0 (out), D13 WLAN_LED_N (out), E1 RF1_PA_OUTP (out), E2 RF1_PA_V33P (in), F1 RF1_PA_OUTN (out), F2 RF1_PA_V33N (in)
part C pins: G3 MD30 (io), G4 MD31 (io), G5 DDR_IO_V33D (in), H1 MDQM3 (io), H2 MDQS3 (io), H3 MD28 (io), H4 MD29 (io), H5 DDR_IOL_V33D (in), J1 MD27 (io), J2 MD26 (io), J3 MD25 (io), J4 MD24 (io), J5 DDR_IOC_V12D (in), K1 MD23 (io), K2 MD22 (io), K3 MD21 (io), K4 MD20 (io), L1 MDQS2 (io), L2 MDQM2 (io), L3 MD19 (io), L4 MD18 (io), L5 DDR_IOR_V09D (in), M1 MD17 (io), M2 MD16 (io), M3 MCKE (io), M4 MODT (io), M5 DDR_IO_V33D (in), M6 DDR_IO_V33D (in), M7 DDR_IOL_V33D (in), M8 DDR_IOR_V09D (in), M9 DDR_IO_V33D (in), M10 DDR_IOC_V12D (in), N1 MCK_P (io), N2 MCK_N (io), N3 MWE_N (io), N4 MRAS_N (io), N5 DDR_IO_V33D (in), N6 MD14 (io), N7 MD11 (io), N8 DDR_IO_V33D (in), N9 DDR_IO_V33D (in), P1 MCAS_N (io), P2 MBA0 (io), P3 MBA1 (io), P4 MA7 (io), P5 MA11 (io), P6 MD13 (io), P7 MD10 (io), P8 MD6 (io), P9 MD1 (io), P10 MD0 (io), R1 MBA2 (io), R2 MCS_N (io), R3 MA0 (io), R4 MA8 (io), R5 MA12 (io), R6 MD12 (io), R7 MD9 (io), R8 MD5 (io), R9 MD2 (io), T1 MA1 (io), T2 MA2 (io), T3 MA5 (io), T4 MA9 (io), T5 MA13 (io), T6 MDQM1 (io), T7 MD8 (io), T8 MD4 (io), T9 MD3 (io), U1 MA3 (io), U2 MA4 (io), U3 MA6 (io), U4 MA10 (io), U5 MD15 (io), U6 MDQS1 (io), U7 MD7 (io), U8 MDQS0 (io), U9 MDQM0 (io)
part D pins: A13 JTAG_TMS (in), A14 PORST_N (in), A15 SPI_CS1 (out), A16 SPI_CLK (out), A17 TXD2 (out), B13 JTAG_TCLK (in), B14 SPI_MISO (in), B15 SPI_CS0 (out), B16 RXD2 (in), B17 I2C_SD (out), C12 GPIO0 (io), C13 JTAG_TRST_N (in), C14 SPI_MOSI (out), C15 I2C_SCLK (io), D6 NC (io), D12 JTAG_TDO (out), E12 JTAG_TDI (in), G13 TXD (out), G14 RTS_N (out), G15 DTR_N (out), G16 DCD_N (in), G17 DSR_N (in), H13 CTS_N (in), H14 RIN (in), H15 RXD (in)
part E pins: C17 UPHY1_PADP (io), D14 UPHY1_VDDL_V12D (in), D15 UPHY1_ID (io), D17 UPHY1_PADM (io), E13 UPHY1_VDDA_V33A (in), E14 UPHY0_VDDL_V12D (in), E15 UPHY1_VBUS (io), E16 UPHY1_VRES (io), E17 UPHY0_PADP (io), F13 UPHY0_VDDA_V33A (in), F14 UPHY0_ID (io), F15 UPHY0_VBUS (io), F16 UPHY0_VRES (io), F17 UPHY0_PADM (io)
part F pins: A12 EPHY_LED1_N (out), B12 EPHY_LED0_N (out), C11 EPHY_LED4_N (out), C16 MDIO (io), D11 EPHY_LED3_N (out), D16 MDC (out), E11 EPHY_LED2_N (out), H16 GE1_TXD3 (out), H17 GE1_TXD2 (out), J14 GE1_TXCLK (io), J15 GE1_TXEN (out), J16 GE1_TXD0 (out), J17 GE1_TXD1 (out), K14 GE1_RXCLK (io), K15 GE1_RXD3 (in), L14 GE1_RXD2 (in), L15 GE1_RXD1 (in), M14 GE1_RXD0 (in), M15 GE1_RXDV (in), P11 EPHY_V33A (in), P12 EPHY_V33A (in), P13 EPHY_V33A (in), R10 EPHY_RXP_p4 (in), R11 EPHY_RXN_p4 (in), R12 EPHY_TXP_p3 (out), R13 EPHY_TXN_p3 (out), R14 EPHY_RXN_p1 (in), R15 EPHY_TXP_p0 (out), R16 EPHY_RXP_p0 (in), T10 EPHY_TXP_p4 (out), T11 EPHY_RXN_p3 (in), T12 EPHY_TXP_p2 (out), T13 EPHY_RXP_p2 (in), T14 EPHY_RXP_p1 (in), T15 EPHY_TXN_p0 (out), T16 EPHY_RXN_p0 (in), U10 EPHY_TXN_p4 (out), U11 EPHY_RXP_p3 (in), U12 EPHY_TXN_p2 (out), U13 EPHY_RXN_p2 (in), U14 EPHY_TXN_p1 (out), U15 EPHY_TXP_p1 (out), U16 EPHY_REF_RES (io)
part G pins: A1 GND (in), B1 GND (in), C2 GND (in), D3 GND (in), D4 GND (in), E4 GND (in), E5 GND (in), E6 GND (in), E7 GND (in), E8 GND (in), E9 GND (in), E10 GND (in), F4 GND (in), F5 GND (in), F6 GND (in), F7 GND (in), F8 GND (in), F9 GND (in), F10 GND (in), F11 GND (in), F12 SOC_CO_V12D (in), G1 GND (in), G2 GND (in), G6 GND (in), G7 GND (in), G8 GND (in), G9 GND (in), G10 GND (in), G11 GND (in), G12 SOC_CO_V12D (in), H6 GND (in), H7 GND (in), H8 GND (in), H9 GND (in), H10 GND (in), H11 GND (in), H12 BPLL_DVDD_V12D (in), J6 GND (in), J7 GND (in), J8 GND (in), J9 GND (in), J10 GND (in), J11 GND (in), J12 CPLL_DVDD_V12D (in), J13 SOC_IO_V33D (in), K5 SOC_CO_V12D (in), K6 GND (in), K7 GND (in), K8 GND (in), K9 GND (in), K10 GND (in), K11 GND (in), K12 GND (in), K13 SOC_IO_V33D (in), L6 GND (in), L7 GND (in), L8 GND (in), L9 GND (in), L10 GND (in), L11 GND (in), L12 GND (in), L13 BPLL_AVDD_V12A (in), M11 GND (in), M12 GND (in), M13 CPLL_AVDD_V12A (in), N10 SOC_CO_V12D (in), N11 GND (in), N12 GND (in)
part H pins: K16 DCDC_VSSA (in), K17 DCDC_VSSD (in), L16 FB (in), L17 LGATE (in), M16 VOUT_1P2 (in), M17 DCDC_V33D (in), N13 DCDC_VSSA (in), N14 DCDC_V33A (in), N15 COMP (in), N16 VOUT_1P2 (in), N17 UGATE (in), P14 OUT_FB_1P8 (in), P15 EXT_LDO_1P8 (in), P16 VFB_1P2 (in), P17 DIS_SW (in), R17 EXT_LDO_1P5 (in), T17 VIN_1P5 (in), U17 VIN_1P5 (in)

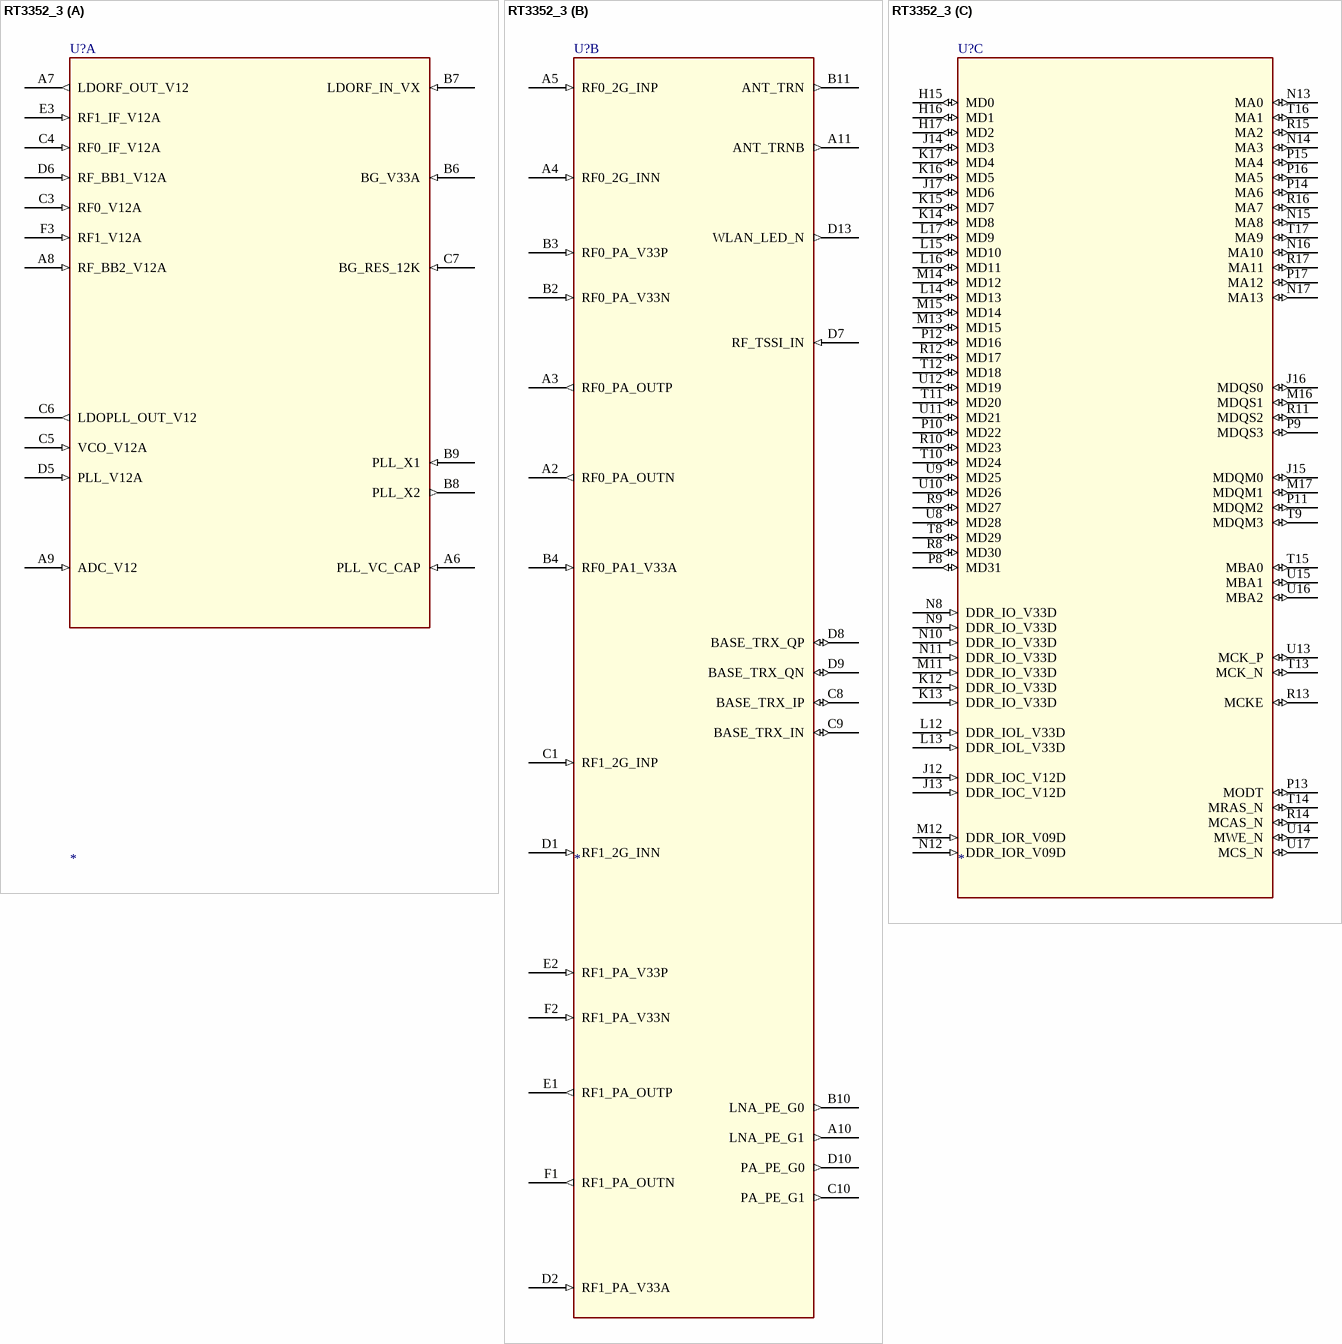
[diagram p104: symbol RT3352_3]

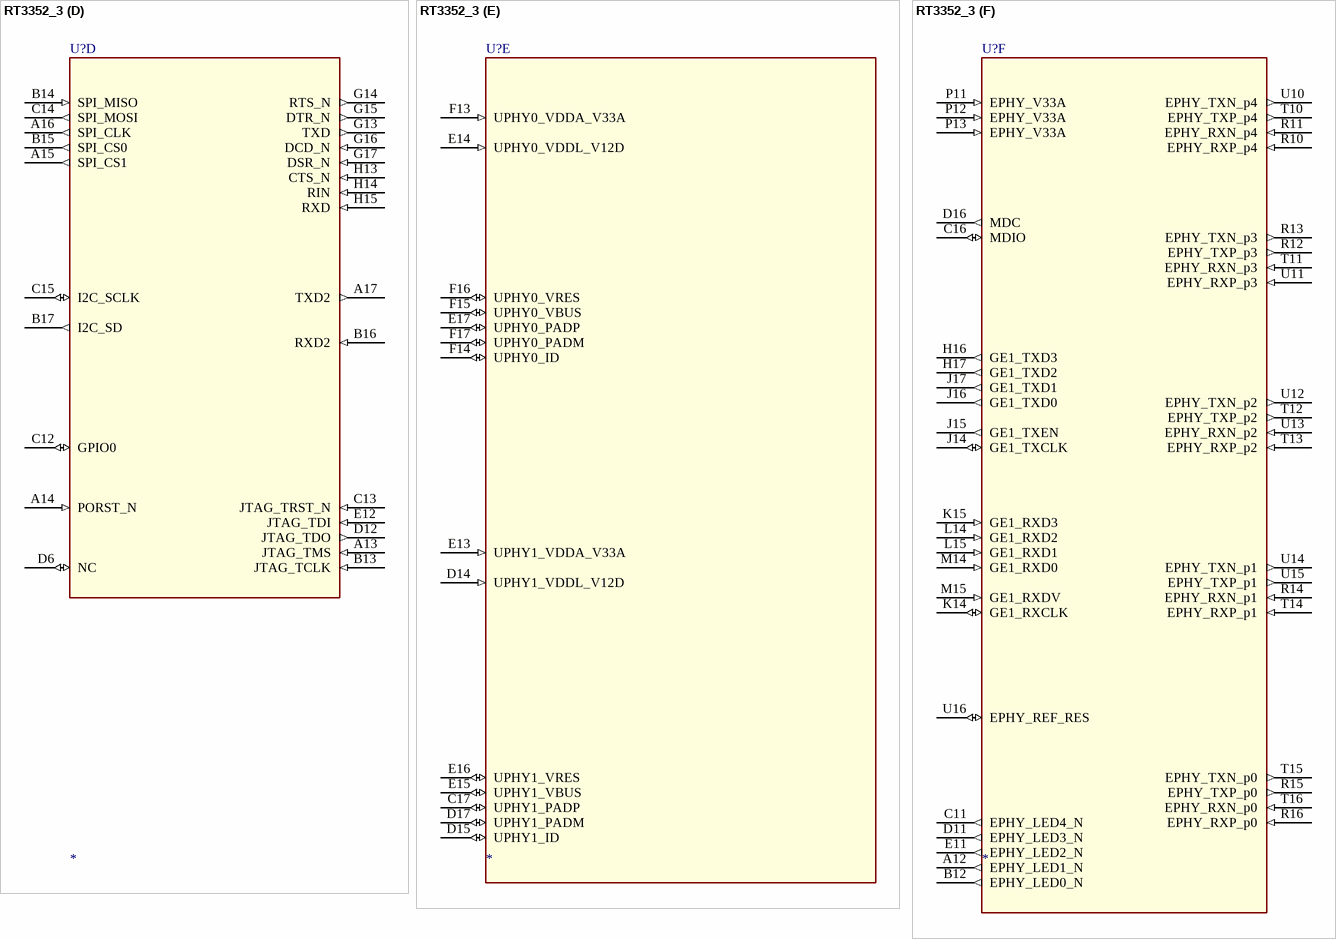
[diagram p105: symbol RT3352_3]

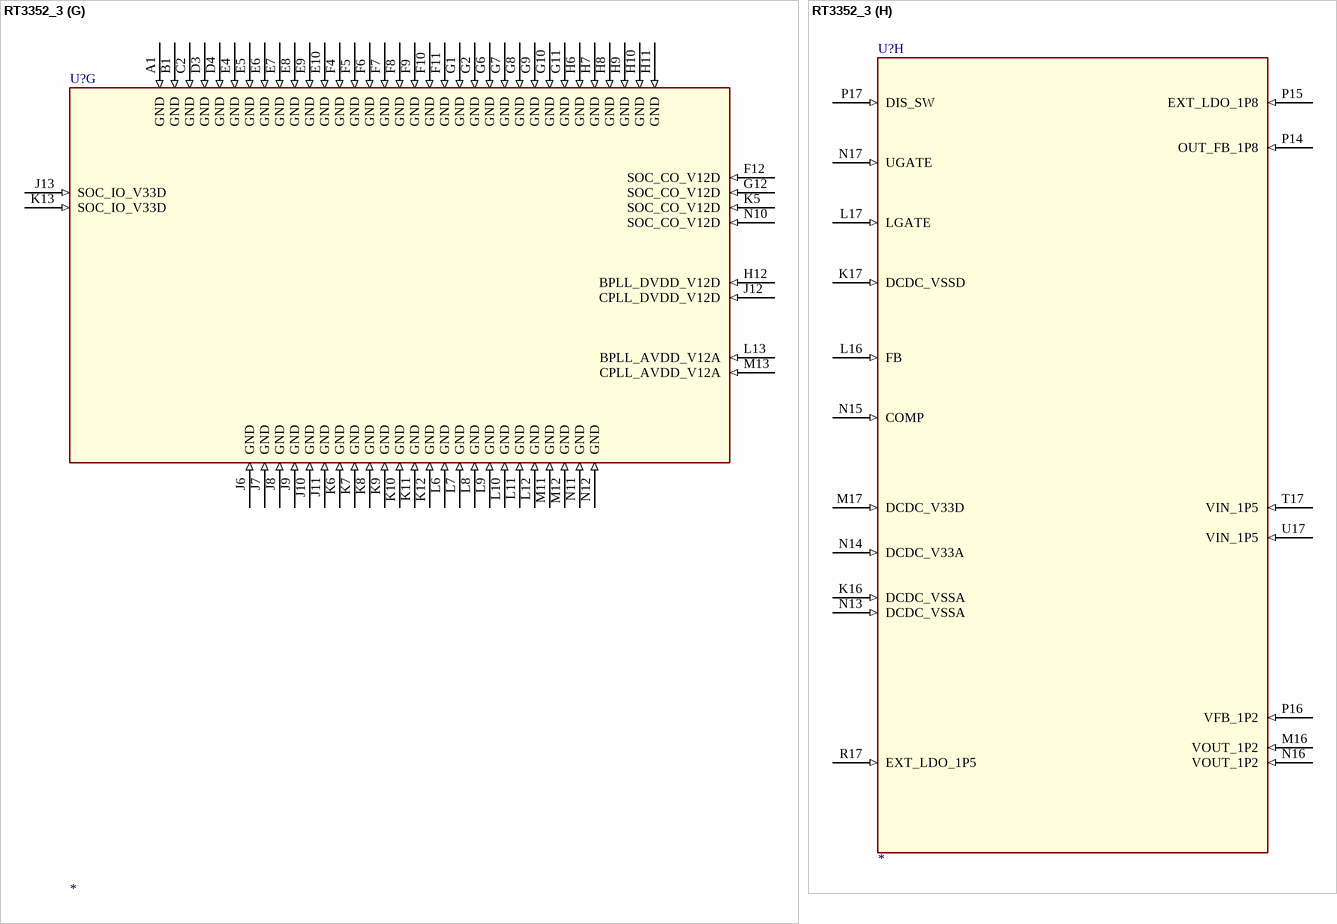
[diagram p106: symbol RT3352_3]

## RT3352_3
designator U?
part A pins: A6 PLL_VC_CAP (in), A7 LDORF_OUT_V12 (out), A8 RF_BB2_V12A (in), A9 ADC_V12 (in), B6 BG_V33A (in), B7 LDORF_IN_VX (in), B8 PLL_X2 (out), B9 PLL_X1 (in), C3 RF0_V12A (in), C4 RF0_IF_V12A (in), C5 VCO_V12A (in), C6 LDOPLL_OUT_V12 (out), C7 BG_RES_12K (in), D5 PLL_V12A (in), D6 RF_BB1_V12A (in), E3 RF1_IF_V12A (in), F3 RF1_V12A (in)
part B pins: A2 RF0_PA_OUTN (out), A3 RF0_PA_OUTP (out), A4 RF0_2G_INN (in), A5 RF0_2G_INP (in), A10 LNA_PE_G1 (out), A11 ANT_TRNB (out), B2 RF0_PA_V33N (in), B3 RF0_PA_V33P (in), B4 RF0_PA1_V33A (in), B10 LNA_PE_G0 (out), B11 ANT_TRN (out), C1 RF1_2G_INP (in), C8 BASE_TRX_IP (io), C9 BASE_TRX_IN (io), C10 PA_PE_G1 (out), D1 RF1_2G_INN (in), D2 RF1_PA_V33A (in), D7 RF_TSSI_IN (in), D8 BASE_TRX_QP (io), D9 BASE_TRX_QN (io), D10 PA_PE_G0 (out), D13 WLAN_LED_N (out), E1 RF1_PA_OUTP (out), E2 RF1_PA_V33P (in), F1 RF1_PA_OUTN (out), F2 RF1_PA_V33N (in)
part C pins: H15 MD0 (io), H16 MD1 (io), H17 MD2 (io), J12 DDR_IOC_V12D (in), J13 DDR_IOC_V12D (in), J14 MD3 (io), J15 MDQM0 (io), J16 MDQS0 (io), J17 MD6 (io), K12 DDR_IO_V33D (in), K13 DDR_IO_V33D (in), K14 MD8 (io), K15 MD7 (io), K16 MD5 (io), K17 MD4 (io), L12 DDR_IOL_V33D (in), L13 DDR_IOL_V33D (in), L14 MD13 (io), L15 MD10 (io), L16 MD11 (io), L17 MD9 (io), M11 DDR_IO_V33D (in), M12 DDR_IOR_V09D (in), M13 MD15 (io), M14 MD12 (io), M15 MD14 (io), M16 MDQS1 (io), M17 MDQM1 (io), N8 DDR_IO_V33D (in), N9 DDR_IO_V33D (in), N10 DDR_IO_V33D (in), N11 DDR_IO_V33D (in), N12 DDR_IOR_V09D (in), N13 MA0 (io), N14 MA3 (io), N15 MA8 (io), N16 MA10 (io), N17 MA13 (io), P8 MD31 (io), P9 MDQS3 (io), P10 MD22 (io), P11 MDQM2 (io), P12 MD16 (io), P13 MODT (io), P14 MA6 (io), P15 MA4 (io), P16 MA5 (io), P17 MA12 (io), R8 MD30 (io), R9 MD27 (io), R10 MD23 (io), R11 MDQS2 (io), R12 MD17 (io), R13 MCKE (io), R14 MCAS_N (io), R15 MA2 (io), R16 MA7 (io), R17 MA11 (io), T8 MD29 (io), T9 MDQM3 (io), T10 MD24 (io), T11 MD20 (io), T12 MD18 (io), T13 MCK_N (io), T14 MRAS_N (io), T15 MBA0 (io), T16 MA1 (io), T17 MA9 (io), U8 MD28 (io), U9 MD25 (io), U10 MD26 (io), U11 MD21 (io), U12 MD19 (io), U13 MCK_P (io), U14 MWE_N (io), U15 MBA1 (io), U16 MBA2 (io), U17 MCS_N (io)
part D pins: A13 JTAG_TMS (in), A14 PORST_N (in), A15 SPI_CS1 (out), A16 SPI_CLK (out), A17 TXD2 (out), B13 JTAG_TCLK (in), B14 SPI_MISO (in), B15 SPI_CS0 (out), B16 RXD2 (in), B17 I2C_SD (out), C12 GPIO0 (io), C13 JTAG_TRST_N (in), C14 SPI_MOSI (out), C15 I2C_SCLK (io), D6 NC (io), D12 JTAG_TDO (out), E12 JTAG_TDI (in), G13 TXD (out), G14 RTS_N (out), G15 DTR_N (out), G16 DCD_N (in), G17 DSR_N (in), H13 CTS_N (in), H14 RIN (in), H15 RXD (in)
part E pins: C17 UPHY1_PADP (io), D14 UPHY1_VDDL_V12D (in), D15 UPHY1_ID (io), D17 UPHY1_PADM (io), E13 UPHY1_VDDA_V33A (in), E14 UPHY0_VDDL_V12D (in), E15 UPHY1_VBUS (io), E16 UPHY1_VRES (io), E17 UPHY0_PADP (io), F13 UPHY0_VDDA_V33A (in), F14 UPHY0_ID (io), F15 UPHY0_VBUS (io), F16 UPHY0_VRES (io), F17 UPHY0_PADM (io)
part F pins: A12 EPHY_LED1_N (out), B12 EPHY_LED0_N (out), C11 EPHY_LED4_N (out), C16 MDIO (io), D11 EPHY_LED3_N (out), D16 MDC (out), E11 EPHY_LED2_N (out), H16 GE1_TXD3 (out), H17 GE1_TXD2 (out), J14 GE1_TXCLK (io), J15 GE1_TXEN (out), J16 GE1_TXD0 (out), J17 GE1_TXD1 (out), K14 GE1_RXCLK (io), K15 GE1_RXD3 (in), L14 GE1_RXD2 (in), L15 GE1_RXD1 (in), M14 GE1_RXD0 (in), M15 GE1_RXDV (in), P11 EPHY_V33A (in), P12 EPHY_V33A (in), P13 EPHY_V33A (in), R10 EPHY_RXP_p4 (in), R11 EPHY_RXN_p4 (in), R12 EPHY_TXP_p3 (out), R13 EPHY_TXN_p3 (out), R14 EPHY_RXN_p1 (in), R15 EPHY_TXP_p0 (out), R16 EPHY_RXP_p0 (in), T10 EPHY_TXP_p4 (out), T11 EPHY_RXN_p3 (in), T12 EPHY_TXP_p2 (out), T13 EPHY_RXP_p2 (in), T14 EPHY_RXP_p1 (in), T15 EPHY_TXN_p0 (out), T16 EPHY_RXN_p0 (in), U10 EPHY_TXN_p4 (out), U11 EPHY_RXP_p3 (in), U12 EPHY_TXN_p2 (out), U13 EPHY_RXN_p2 (in), U14 EPHY_TXN_p1 (out), U15 EPHY_TXP_p1 (out), U16 EPHY_REF_RES (io)
part G pins: A1 GND (in), B1 GND (in), C2 GND (in), D3 GND (in), D4 GND (in), E4 GND (in), E5 GND (in), E6 GND (in), E7 GND (in), E8 GND (in), E9 GND (in), E10 GND (in), F4 GND (in), F5 GND (in), F6 GND (in), F7 GND (in), F8 GND (in), F9 GND (in), F10 GND (in), F11 GND (in), F12 SOC_CO_V12D (in), G1 GND (in), G2 GND (in), G6 GND (in), G7 GND (in), G8 GND (in), G9 GND (in), G10 GND (in), G11 GND (in), G12 SOC_CO_V12D (in), H6 GND (in), H7 GND (in), H8 GND (in), H9 GND (in), H10 GND (in), H11 GND (in), H12 BPLL_DVDD_V12D (in), J6 GND (in), J7 GND (in), J8 GND (in), J9 GND (in), J10 GND (in), J11 GND (in), J12 CPLL_DVDD_V12D (in), J13 SOC_IO_V33D (in), K5 SOC_CO_V12D (in), K6 GND (in), K7 GND (in), K8 GND (in), K9 GND (in), K10 GND (in), K11 GND (in), K12 GND (in), K13 SOC_IO_V33D (in), L6 GND (in), L7 GND (in), L8 GND (in), L9 GND (in), L10 GND (in), L11 GND (in), L12 GND (in), L13 BPLL_AVDD_V12A (in), M11 GND (in), M12 GND (in), M13 CPLL_AVDD_V12A (in), N10 SOC_CO_V12D (in), N11 GND (in), N12 GND (in)
part H pins: K16 DCDC_VSSA (in), K17 DCDC_VSSD (in), L16 FB (in), L17 LGATE (in), M16 VOUT_1P2 (in), M17 DCDC_V33D (in), N13 DCDC_VSSA (in), N14 DCDC_V33A (in), N15 COMP (in), N16 VOUT_1P2 (in), N17 UGATE (in), P14 OUT_FB_1P8 (in), P15 EXT_LDO_1P8 (in), P16 VFB_1P2 (in), P17 DIS_SW (in), R17 EXT_LDO_1P5 (in), T17 VIN_1P5 (in), U17 VIN_1P5 (in)

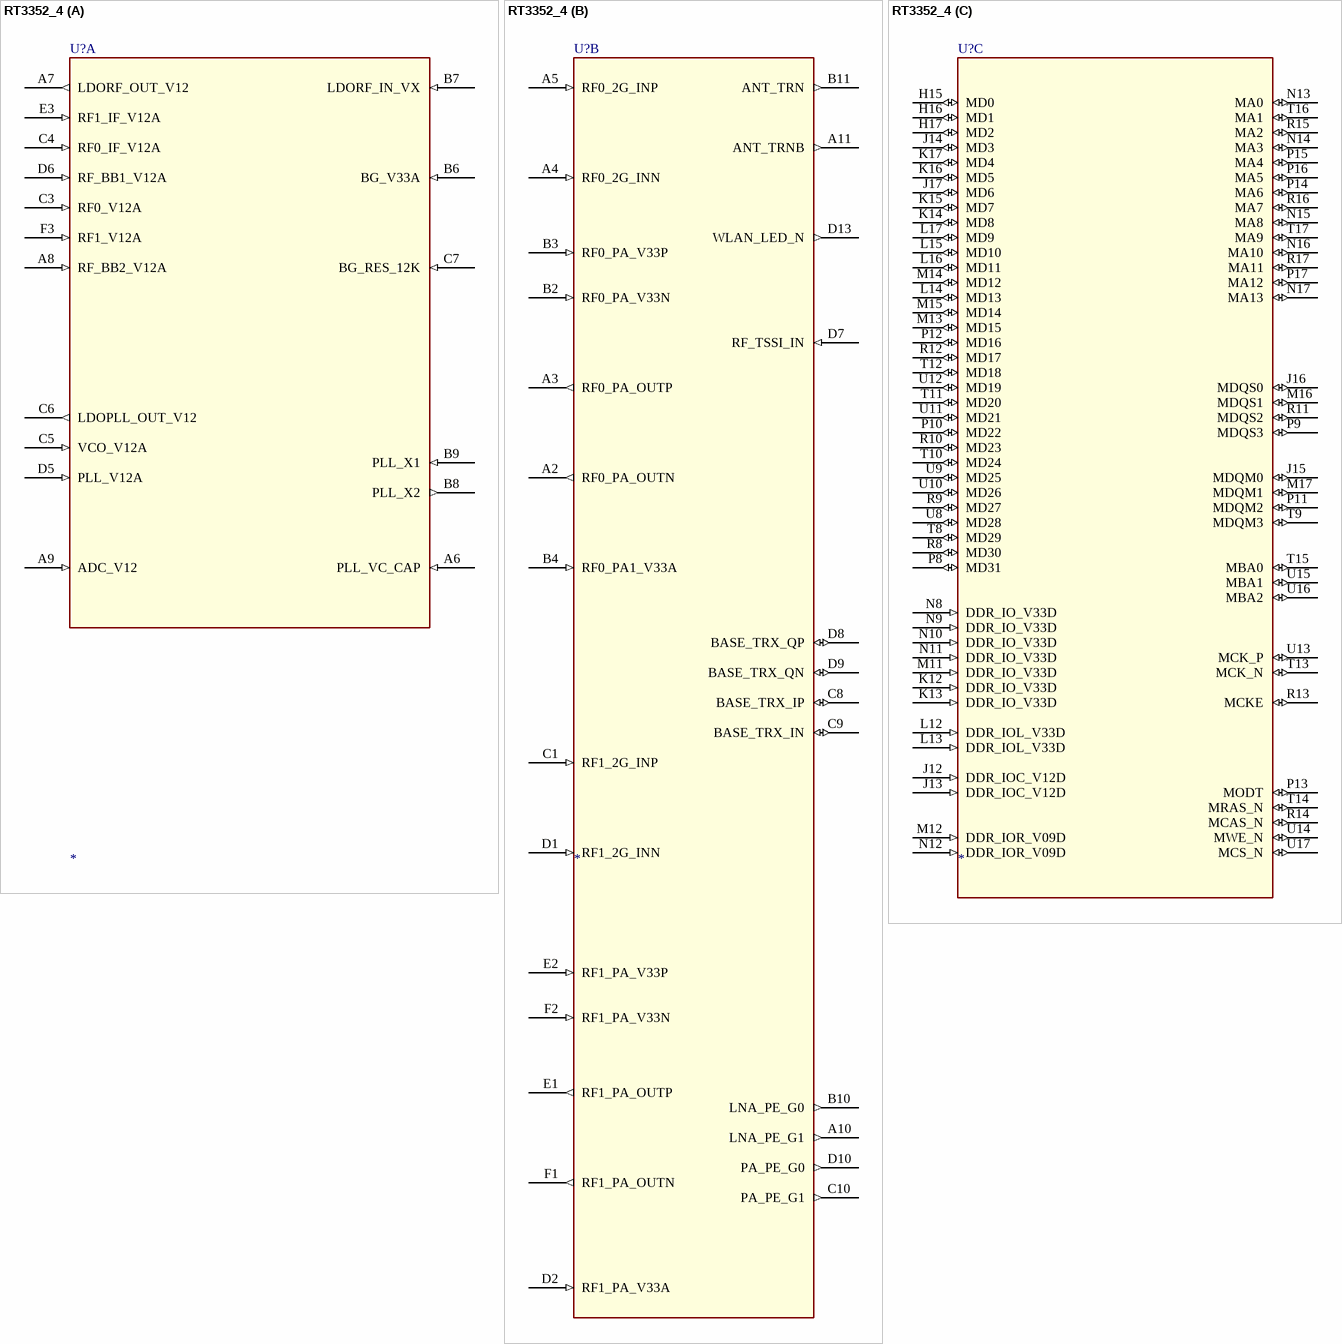
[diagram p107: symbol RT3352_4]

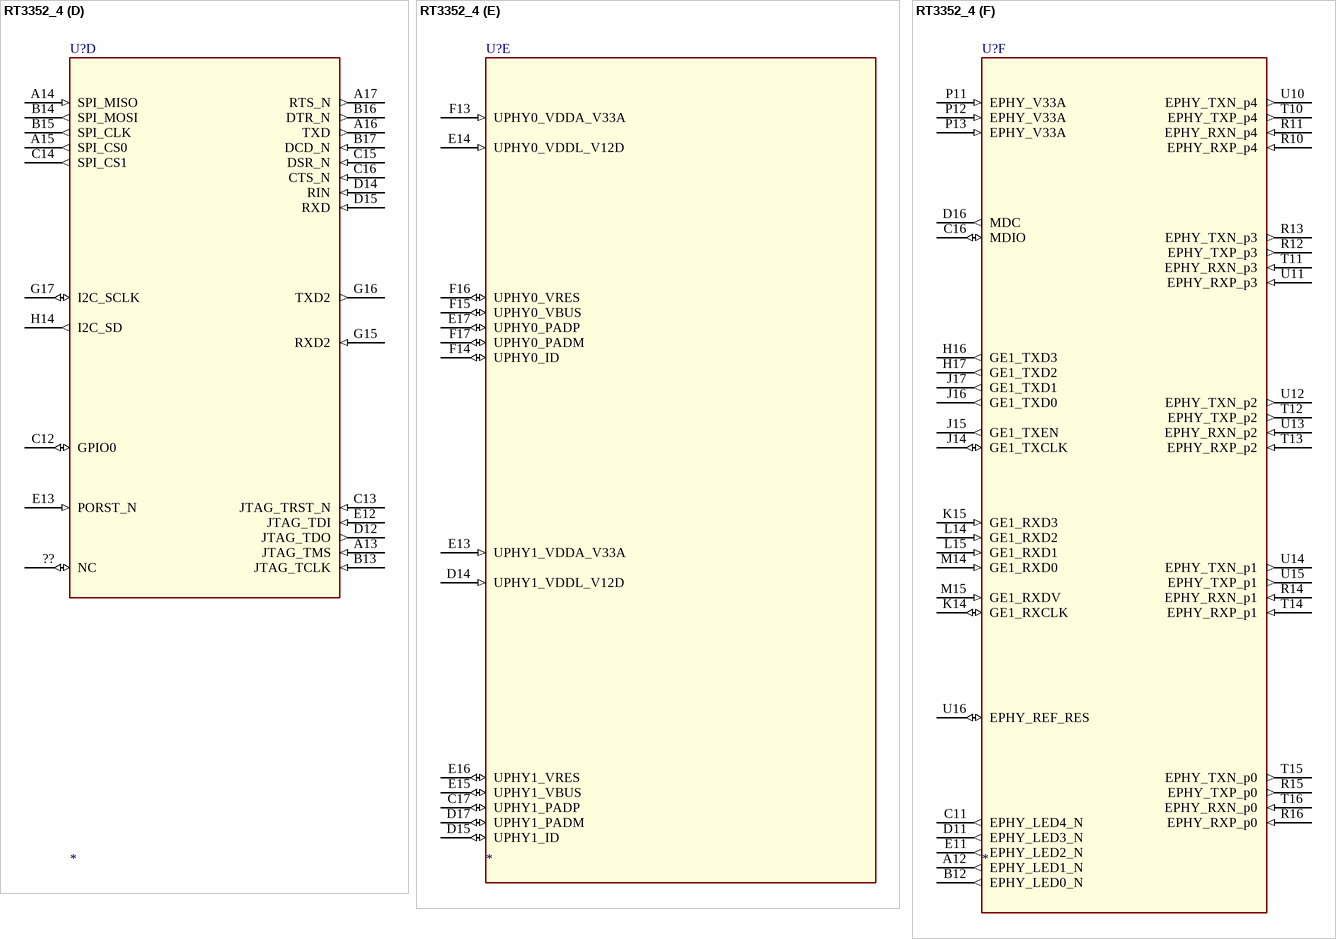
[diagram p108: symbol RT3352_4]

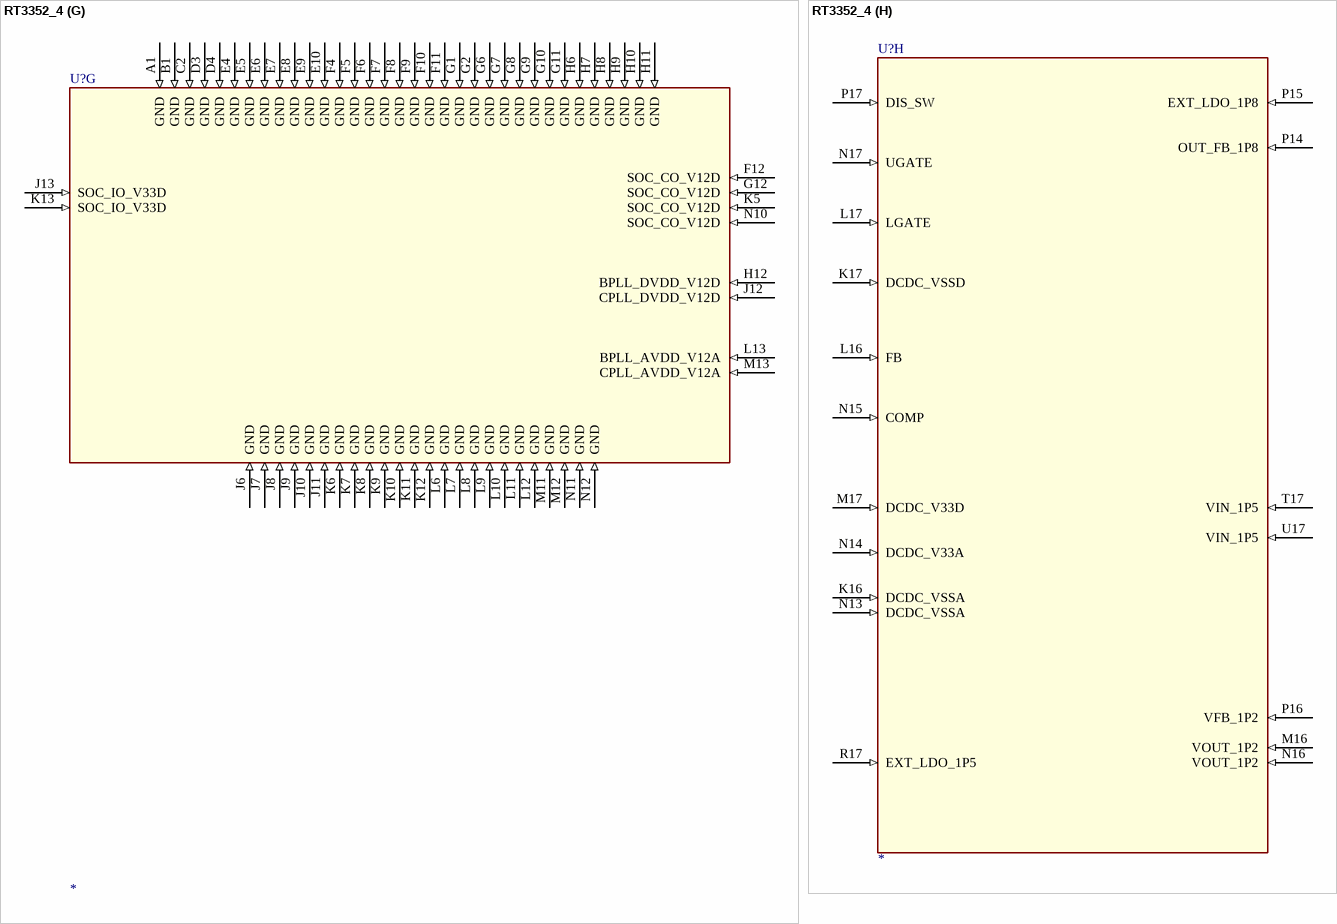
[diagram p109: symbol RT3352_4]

## RT3352_4
designator U?
part A pins: A6 PLL_VC_CAP (in), A7 LDORF_OUT_V12 (out), A8 RF_BB2_V12A (in), A9 ADC_V12 (in), B6 BG_V33A (in), B7 LDORF_IN_VX (in), B8 PLL_X2 (out), B9 PLL_X1 (in), C3 RF0_V12A (in), C4 RF0_IF_V12A (in), C5 VCO_V12A (in), C6 LDOPLL_OUT_V12 (out), C7 BG_RES_12K (in), D5 PLL_V12A (in), D6 RF_BB1_V12A (in), E3 RF1_IF_V12A (in), F3 RF1_V12A (in)
part B pins: A2 RF0_PA_OUTN (out), A3 RF0_PA_OUTP (out), A4 RF0_2G_INN (in), A5 RF0_2G_INP (in), A10 LNA_PE_G1 (out), A11 ANT_TRNB (out), B2 RF0_PA_V33N (in), B3 RF0_PA_V33P (in), B4 RF0_PA1_V33A (in), B10 LNA_PE_G0 (out), B11 ANT_TRN (out), C1 RF1_2G_INP (in), C8 BASE_TRX_IP (io), C9 BASE_TRX_IN (io), C10 PA_PE_G1 (out), D1 RF1_2G_INN (in), D2 RF1_PA_V33A (in), D7 RF_TSSI_IN (in), D8 BASE_TRX_QP (io), D9 BASE_TRX_QN (io), D10 PA_PE_G0 (out), D13 WLAN_LED_N (out), E1 RF1_PA_OUTP (out), E2 RF1_PA_V33P (in), F1 RF1_PA_OUTN (out), F2 RF1_PA_V33N (in)
part C pins: H15 MD0 (io), H16 MD1 (io), H17 MD2 (io), J12 DDR_IOC_V12D (in), J13 DDR_IOC_V12D (in), J14 MD3 (io), J15 MDQM0 (io), J16 MDQS0 (io), J17 MD6 (io), K12 DDR_IO_V33D (in), K13 DDR_IO_V33D (in), K14 MD8 (io), K15 MD7 (io), K16 MD5 (io), K17 MD4 (io), L12 DDR_IOL_V33D (in), L13 DDR_IOL_V33D (in), L14 MD13 (io), L15 MD10 (io), L16 MD11 (io), L17 MD9 (io), M11 DDR_IO_V33D (in), M12 DDR_IOR_V09D (in), M13 MD15 (io), M14 MD12 (io), M15 MD14 (io), M16 MDQS1 (io), M17 MDQM1 (io), N8 DDR_IO_V33D (in), N9 DDR_IO_V33D (in), N10 DDR_IO_V33D (in), N11 DDR_IO_V33D (in), N12 DDR_IOR_V09D (in), N13 MA0 (io), N14 MA3 (io), N15 MA8 (io), N16 MA10 (io), N17 MA13 (io), P8 MD31 (io), P9 MDQS3 (io), P10 MD22 (io), P11 MDQM2 (io), P12 MD16 (io), P13 MODT (io), P14 MA6 (io), P15 MA4 (io), P16 MA5 (io), P17 MA12 (io), R8 MD30 (io), R9 MD27 (io), R10 MD23 (io), R11 MDQS2 (io), R12 MD17 (io), R13 MCKE (io), R14 MCAS_N (io), R15 MA2 (io), R16 MA7 (io), R17 MA11 (io), T8 MD29 (io), T9 MDQM3 (io), T10 MD24 (io), T11 MD20 (io), T12 MD18 (io), T13 MCK_N (io), T14 MRAS_N (io), T15 MBA0 (io), T16 MA1 (io), T17 MA9 (io), U8 MD28 (io), U9 MD25 (io), U10 MD26 (io), U11 MD21 (io), U12 MD19 (io), U13 MCK_P (io), U14 MWE_N (io), U15 MBA1 (io), U16 MBA2 (io), U17 MCS_N (io)
part D pins: ?? NC (io), A13 JTAG_TMS (in), A14 SPI_MISO (in), A15 SPI_CS0 (out), A16 TXD (out), A17 RTS_N (out), B13 JTAG_TCLK (in), B14 SPI_MOSI (out), B15 SPI_CLK (out), B16 DTR_N (out), B17 DCD_N (in), C12 GPIO0 (io), C13 JTAG_TRST_N (in), C14 SPI_CS1 (out), C15 DSR_N (in), C16 CTS_N (in), D12 JTAG_TDO (out), D14 RIN (in), D15 RXD (in), E12 JTAG_TDI (in), E13 PORST_N (in), G15 RXD2 (in), G16 TXD2 (out), G17 I2C_SCLK (io), H14 I2C_SD (out)
part E pins: C17 UPHY1_PADP (io), D14 UPHY1_VDDL_V12D (in), D15 UPHY1_ID (io), D17 UPHY1_PADM (io), E13 UPHY1_VDDA_V33A (in), E14 UPHY0_VDDL_V12D (in), E15 UPHY1_VBUS (io), E16 UPHY1_VRES (io), E17 UPHY0_PADP (io), F13 UPHY0_VDDA_V33A (in), F14 UPHY0_ID (io), F15 UPHY0_VBUS (io), F16 UPHY0_VRES (io), F17 UPHY0_PADM (io)
part F pins: A12 EPHY_LED1_N (out), B12 EPHY_LED0_N (out), C11 EPHY_LED4_N (out), C16 MDIO (io), D11 EPHY_LED3_N (out), D16 MDC (out), E11 EPHY_LED2_N (out), H16 GE1_TXD3 (out), H17 GE1_TXD2 (out), J14 GE1_TXCLK (io), J15 GE1_TXEN (out), J16 GE1_TXD0 (out), J17 GE1_TXD1 (out), K14 GE1_RXCLK (io), K15 GE1_RXD3 (in), L14 GE1_RXD2 (in), L15 GE1_RXD1 (in), M14 GE1_RXD0 (in), M15 GE1_RXDV (in), P11 EPHY_V33A (in), P12 EPHY_V33A (in), P13 EPHY_V33A (in), R10 EPHY_RXP_p4 (in), R11 EPHY_RXN_p4 (in), R12 EPHY_TXP_p3 (out), R13 EPHY_TXN_p3 (out), R14 EPHY_RXN_p1 (in), R15 EPHY_TXP_p0 (out), R16 EPHY_RXP_p0 (in), T10 EPHY_TXP_p4 (out), T11 EPHY_RXN_p3 (in), T12 EPHY_TXP_p2 (out), T13 EPHY_RXP_p2 (in), T14 EPHY_RXP_p1 (in), T15 EPHY_TXN_p0 (out), T16 EPHY_RXN_p0 (in), U10 EPHY_TXN_p4 (out), U11 EPHY_RXP_p3 (in), U12 EPHY_TXN_p2 (out), U13 EPHY_RXN_p2 (in), U14 EPHY_TXN_p1 (out), U15 EPHY_TXP_p1 (out), U16 EPHY_REF_RES (io)
part G pins: A1 GND (in), B1 GND (in), C2 GND (in), D3 GND (in), D4 GND (in), E4 GND (in), E5 GND (in), E6 GND (in), E7 GND (in), E8 GND (in), E9 GND (in), E10 GND (in), F4 GND (in), F5 GND (in), F6 GND (in), F7 GND (in), F8 GND (in), F9 GND (in), F10 GND (in), F11 GND (in), F12 SOC_CO_V12D (in), G1 GND (in), G2 GND (in), G6 GND (in), G7 GND (in), G8 GND (in), G9 GND (in), G10 GND (in), G11 GND (in), G12 SOC_CO_V12D (in), H6 GND (in), H7 GND (in), H8 GND (in), H9 GND (in), H10 GND (in), H11 GND (in), H12 BPLL_DVDD_V12D (in), J6 GND (in), J7 GND (in), J8 GND (in), J9 GND (in), J10 GND (in), J11 GND (in), J12 CPLL_DVDD_V12D (in), J13 SOC_IO_V33D (in), K5 SOC_CO_V12D (in), K6 GND (in), K7 GND (in), K8 GND (in), K9 GND (in), K10 GND (in), K11 GND (in), K12 GND (in), K13 SOC_IO_V33D (in), L6 GND (in), L7 GND (in), L8 GND (in), L9 GND (in), L10 GND (in), L11 GND (in), L12 GND (in), L13 BPLL_AVDD_V12A (in), M11 GND (in), M12 GND (in), M13 CPLL_AVDD_V12A (in), N10 SOC_CO_V12D (in), N11 GND (in), N12 GND (in)
part H pins: K16 DCDC_VSSA (in), K17 DCDC_VSSD (in), L16 FB (in), L17 LGATE (in), M16 VOUT_1P2 (in), M17 DCDC_V33D (in), N13 DCDC_VSSA (in), N14 DCDC_V33A (in), N15 COMP (in), N16 VOUT_1P2 (in), N17 UGATE (in), P14 OUT_FB_1P8 (in), P15 EXT_LDO_1P8 (in), P16 VFB_1P2 (in), P17 DIS_SW (in), R17 EXT_LDO_1P5 (in), T17 VIN_1P5 (in), U17 VIN_1P5 (in)

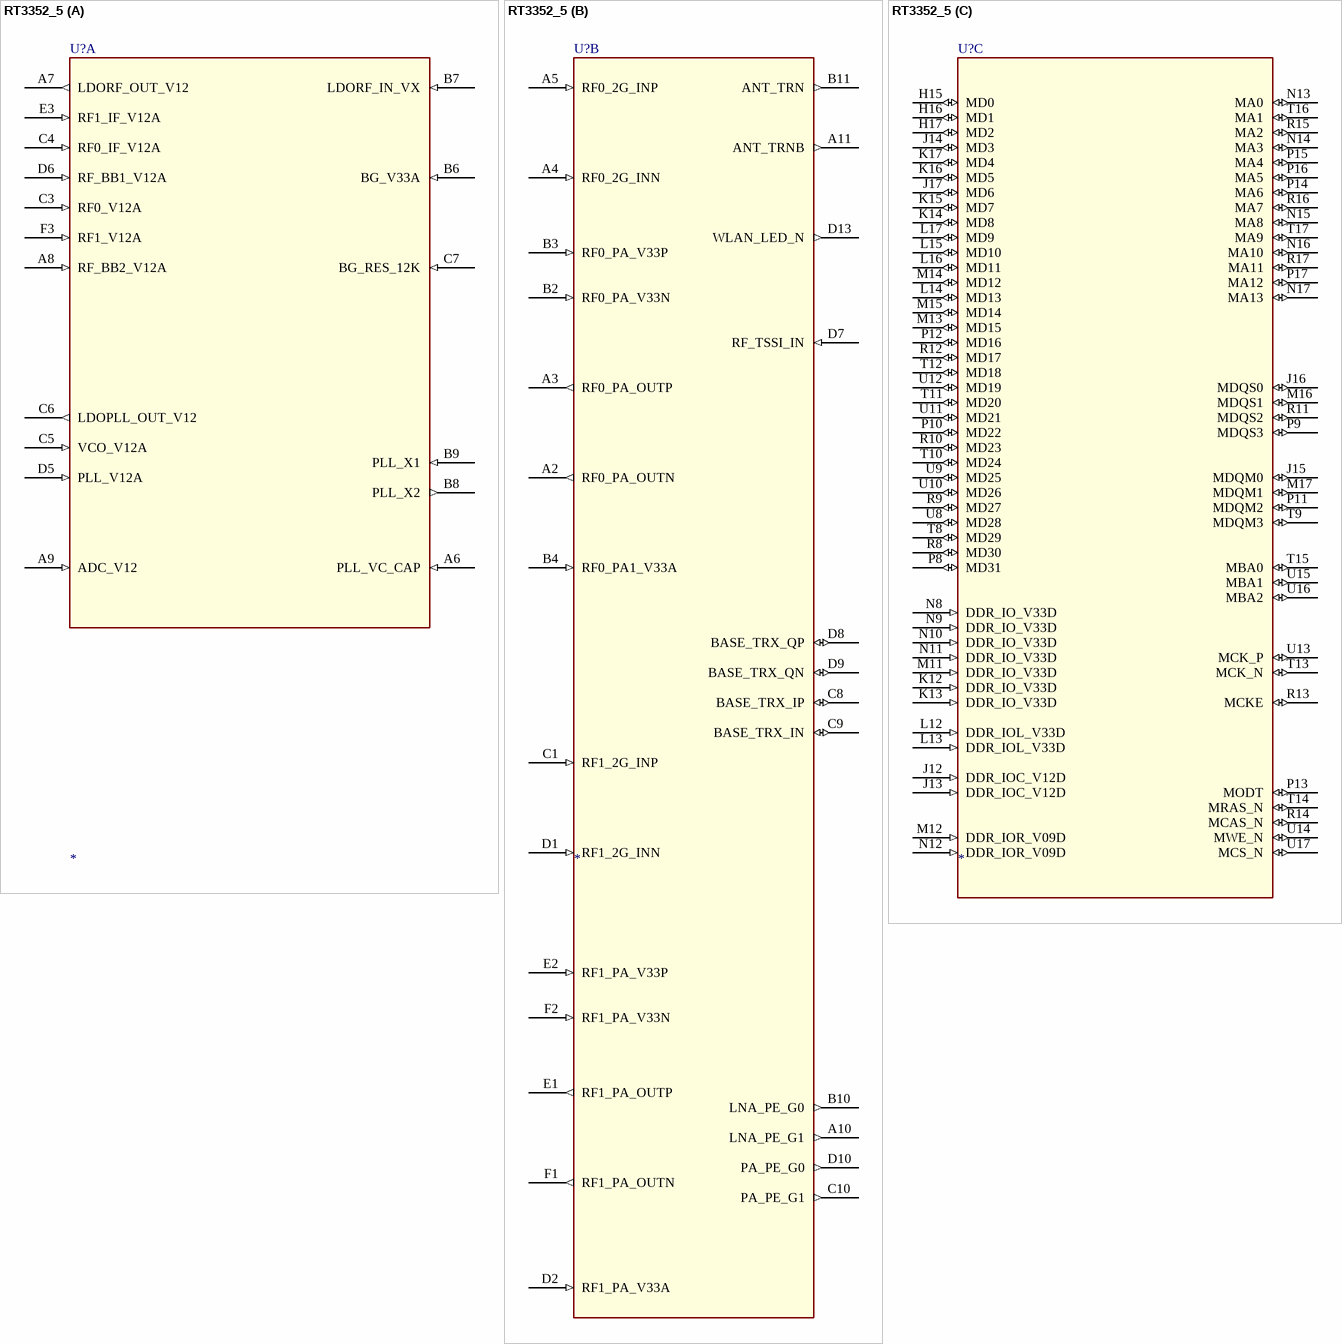
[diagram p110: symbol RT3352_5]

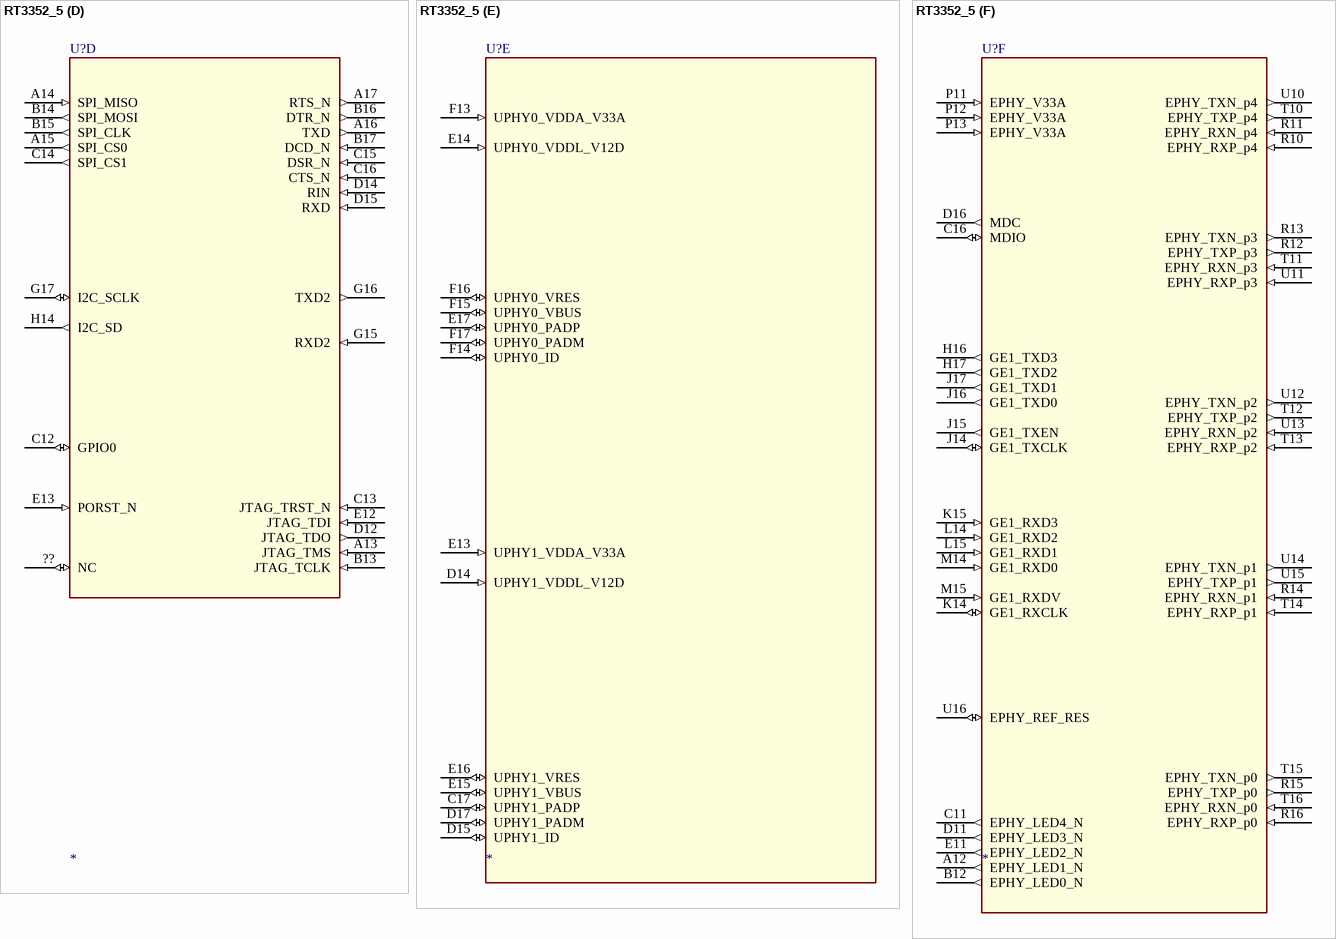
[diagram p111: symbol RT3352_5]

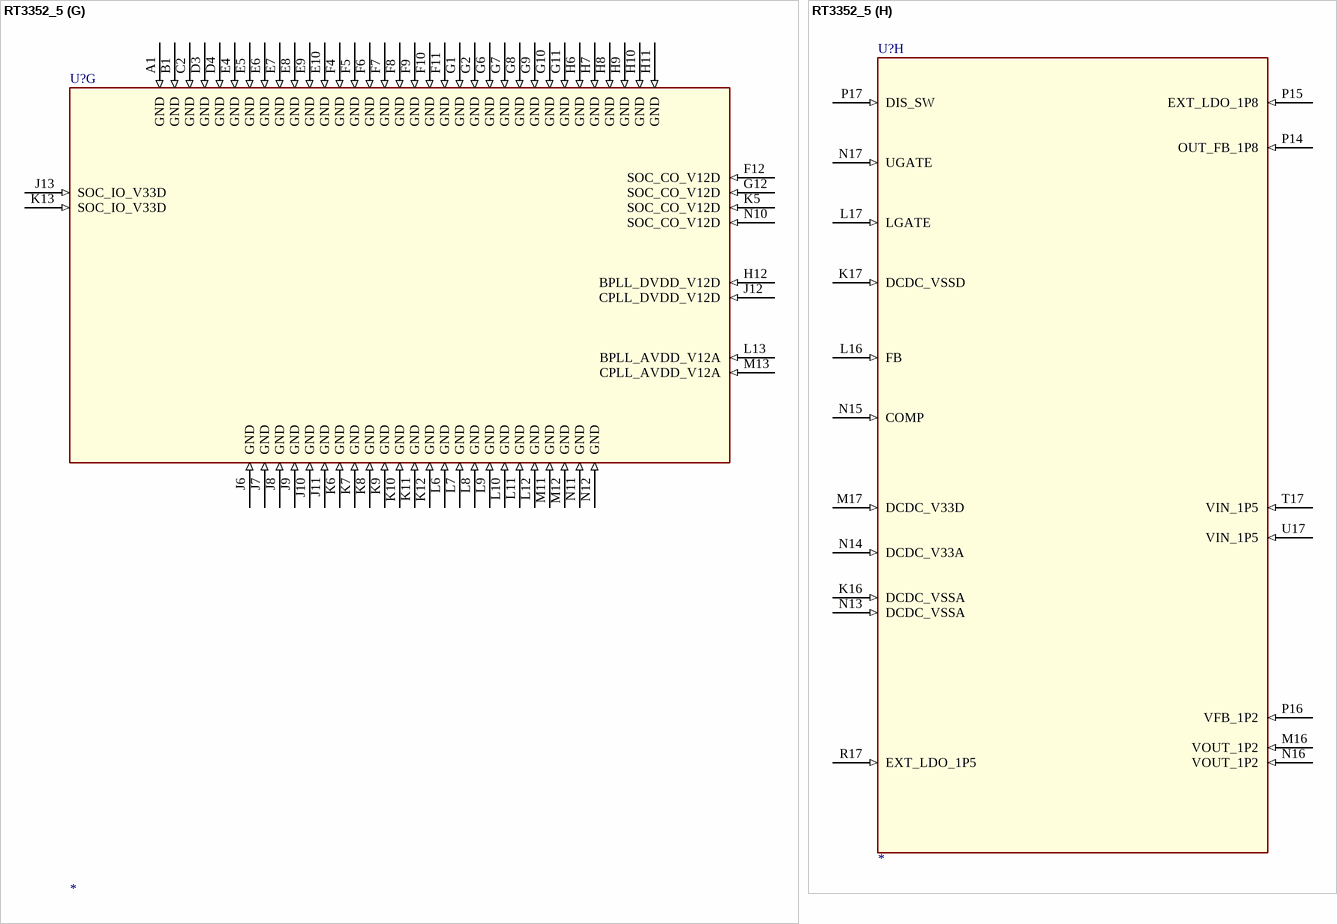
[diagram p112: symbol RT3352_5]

## RT3352_5
designator U?
part A pins: A6 PLL_VC_CAP (in), A7 LDORF_OUT_V12 (out), A8 RF_BB2_V12A (in), A9 ADC_V12 (in), B6 BG_V33A (in), B7 LDORF_IN_VX (in), B8 PLL_X2 (out), B9 PLL_X1 (in), C3 RF0_V12A (in), C4 RF0_IF_V12A (in), C5 VCO_V12A (in), C6 LDOPLL_OUT_V12 (out), C7 BG_RES_12K (in), D5 PLL_V12A (in), D6 RF_BB1_V12A (in), E3 RF1_IF_V12A (in), F3 RF1_V12A (in)
part B pins: A2 RF0_PA_OUTN (out), A3 RF0_PA_OUTP (out), A4 RF0_2G_INN (in), A5 RF0_2G_INP (in), A10 LNA_PE_G1 (out), A11 ANT_TRNB (out), B2 RF0_PA_V33N (in), B3 RF0_PA_V33P (in), B4 RF0_PA1_V33A (in), B10 LNA_PE_G0 (out), B11 ANT_TRN (out), C1 RF1_2G_INP (in), C8 BASE_TRX_IP (io), C9 BASE_TRX_IN (io), C10 PA_PE_G1 (out), D1 RF1_2G_INN (in), D2 RF1_PA_V33A (in), D7 RF_TSSI_IN (in), D8 BASE_TRX_QP (io), D9 BASE_TRX_QN (io), D10 PA_PE_G0 (out), D13 WLAN_LED_N (out), E1 RF1_PA_OUTP (out), E2 RF1_PA_V33P (in), F1 RF1_PA_OUTN (out), F2 RF1_PA_V33N (in)
part C pins: H15 MD0 (io), H16 MD1 (io), H17 MD2 (io), J12 DDR_IOC_V12D (in), J13 DDR_IOC_V12D (in), J14 MD3 (io), J15 MDQM0 (io), J16 MDQS0 (io), J17 MD6 (io), K12 DDR_IO_V33D (in), K13 DDR_IO_V33D (in), K14 MD8 (io), K15 MD7 (io), K16 MD5 (io), K17 MD4 (io), L12 DDR_IOL_V33D (in), L13 DDR_IOL_V33D (in), L14 MD13 (io), L15 MD10 (io), L16 MD11 (io), L17 MD9 (io), M11 DDR_IO_V33D (in), M12 DDR_IOR_V09D (in), M13 MD15 (io), M14 MD12 (io), M15 MD14 (io), M16 MDQS1 (io), M17 MDQM1 (io), N8 DDR_IO_V33D (in), N9 DDR_IO_V33D (in), N10 DDR_IO_V33D (in), N11 DDR_IO_V33D (in), N12 DDR_IOR_V09D (in), N13 MA0 (io), N14 MA3 (io), N15 MA8 (io), N16 MA10 (io), N17 MA13 (io), P8 MD31 (io), P9 MDQS3 (io), P10 MD22 (io), P11 MDQM2 (io), P12 MD16 (io), P13 MODT (io), P14 MA6 (io), P15 MA4 (io), P16 MA5 (io), P17 MA12 (io), R8 MD30 (io), R9 MD27 (io), R10 MD23 (io), R11 MDQS2 (io), R12 MD17 (io), R13 MCKE (io), R14 MCAS_N (io), R15 MA2 (io), R16 MA7 (io), R17 MA11 (io), T8 MD29 (io), T9 MDQM3 (io), T10 MD24 (io), T11 MD20 (io), T12 MD18 (io), T13 MCK_N (io), T14 MRAS_N (io), T15 MBA0 (io), T16 MA1 (io), T17 MA9 (io), U8 MD28 (io), U9 MD25 (io), U10 MD26 (io), U11 MD21 (io), U12 MD19 (io), U13 MCK_P (io), U14 MWE_N (io), U15 MBA1 (io), U16 MBA2 (io), U17 MCS_N (io)
part D pins: ?? NC (io), A13 JTAG_TMS (in), A14 SPI_MISO (in), A15 SPI_CS0 (out), A16 TXD (out), A17 RTS_N (out), B13 JTAG_TCLK (in), B14 SPI_MOSI (out), B15 SPI_CLK (out), B16 DTR_N (out), B17 DCD_N (in), C12 GPIO0 (io), C13 JTAG_TRST_N (in), C14 SPI_CS1 (out), C15 DSR_N (in), C16 CTS_N (in), D12 JTAG_TDO (out), D14 RIN (in), D15 RXD (in), E12 JTAG_TDI (in), E13 PORST_N (in), G15 RXD2 (in), G16 TXD2 (out), G17 I2C_SCLK (io), H14 I2C_SD (out)
part E pins: C17 UPHY1_PADP (io), D14 UPHY1_VDDL_V12D (in), D15 UPHY1_ID (io), D17 UPHY1_PADM (io), E13 UPHY1_VDDA_V33A (in), E14 UPHY0_VDDL_V12D (in), E15 UPHY1_VBUS (io), E16 UPHY1_VRES (io), E17 UPHY0_PADP (io), F13 UPHY0_VDDA_V33A (in), F14 UPHY0_ID (io), F15 UPHY0_VBUS (io), F16 UPHY0_VRES (io), F17 UPHY0_PADM (io)
part F pins: A12 EPHY_LED1_N (out), B12 EPHY_LED0_N (out), C11 EPHY_LED4_N (out), C16 MDIO (io), D11 EPHY_LED3_N (out), D16 MDC (out), E11 EPHY_LED2_N (out), H16 GE1_TXD3 (out), H17 GE1_TXD2 (out), J14 GE1_TXCLK (io), J15 GE1_TXEN (out), J16 GE1_TXD0 (out), J17 GE1_TXD1 (out), K14 GE1_RXCLK (io), K15 GE1_RXD3 (in), L14 GE1_RXD2 (in), L15 GE1_RXD1 (in), M14 GE1_RXD0 (in), M15 GE1_RXDV (in), P11 EPHY_V33A (in), P12 EPHY_V33A (in), P13 EPHY_V33A (in), R10 EPHY_RXP_p4 (in), R11 EPHY_RXN_p4 (in), R12 EPHY_TXP_p3 (out), R13 EPHY_TXN_p3 (out), R14 EPHY_RXN_p1 (in), R15 EPHY_TXP_p0 (out), R16 EPHY_RXP_p0 (in), T10 EPHY_TXP_p4 (out), T11 EPHY_RXN_p3 (in), T12 EPHY_TXP_p2 (out), T13 EPHY_RXP_p2 (in), T14 EPHY_RXP_p1 (in), T15 EPHY_TXN_p0 (out), T16 EPHY_RXN_p0 (in), U10 EPHY_TXN_p4 (out), U11 EPHY_RXP_p3 (in), U12 EPHY_TXN_p2 (out), U13 EPHY_RXN_p2 (in), U14 EPHY_TXN_p1 (out), U15 EPHY_TXP_p1 (out), U16 EPHY_REF_RES (io)
part G pins: A1 GND (in), B1 GND (in), C2 GND (in), D3 GND (in), D4 GND (in), E4 GND (in), E5 GND (in), E6 GND (in), E7 GND (in), E8 GND (in), E9 GND (in), E10 GND (in), F4 GND (in), F5 GND (in), F6 GND (in), F7 GND (in), F8 GND (in), F9 GND (in), F10 GND (in), F11 GND (in), F12 SOC_CO_V12D (in), G1 GND (in), G2 GND (in), G6 GND (in), G7 GND (in), G8 GND (in), G9 GND (in), G10 GND (in), G11 GND (in), G12 SOC_CO_V12D (in), H6 GND (in), H7 GND (in), H8 GND (in), H9 GND (in), H10 GND (in), H11 GND (in), H12 BPLL_DVDD_V12D (in), J6 GND (in), J7 GND (in), J8 GND (in), J9 GND (in), J10 GND (in), J11 GND (in), J12 CPLL_DVDD_V12D (in), J13 SOC_IO_V33D (in), K5 SOC_CO_V12D (in), K6 GND (in), K7 GND (in), K8 GND (in), K9 GND (in), K10 GND (in), K11 GND (in), K12 GND (in), K13 SOC_IO_V33D (in), L6 GND (in), L7 GND (in), L8 GND (in), L9 GND (in), L10 GND (in), L11 GND (in), L12 GND (in), L13 BPLL_AVDD_V12A (in), M11 GND (in), M12 GND (in), M13 CPLL_AVDD_V12A (in), N10 SOC_CO_V12D (in), N11 GND (in), N12 GND (in)
part H pins: K16 DCDC_VSSA (in), K17 DCDC_VSSD (in), L16 FB (in), L17 LGATE (in), M16 VOUT_1P2 (in), M17 DCDC_V33D (in), N13 DCDC_VSSA (in), N14 DCDC_V33A (in), N15 COMP (in), N16 VOUT_1P2 (in), N17 UGATE (in), P14 OUT_FB_1P8 (in), P15 EXT_LDO_1P8 (in), P16 VFB_1P2 (in), P17 DIS_SW (in), R17 EXT_LDO_1P5 (in), T17 VIN_1P5 (in), U17 VIN_1P5 (in)

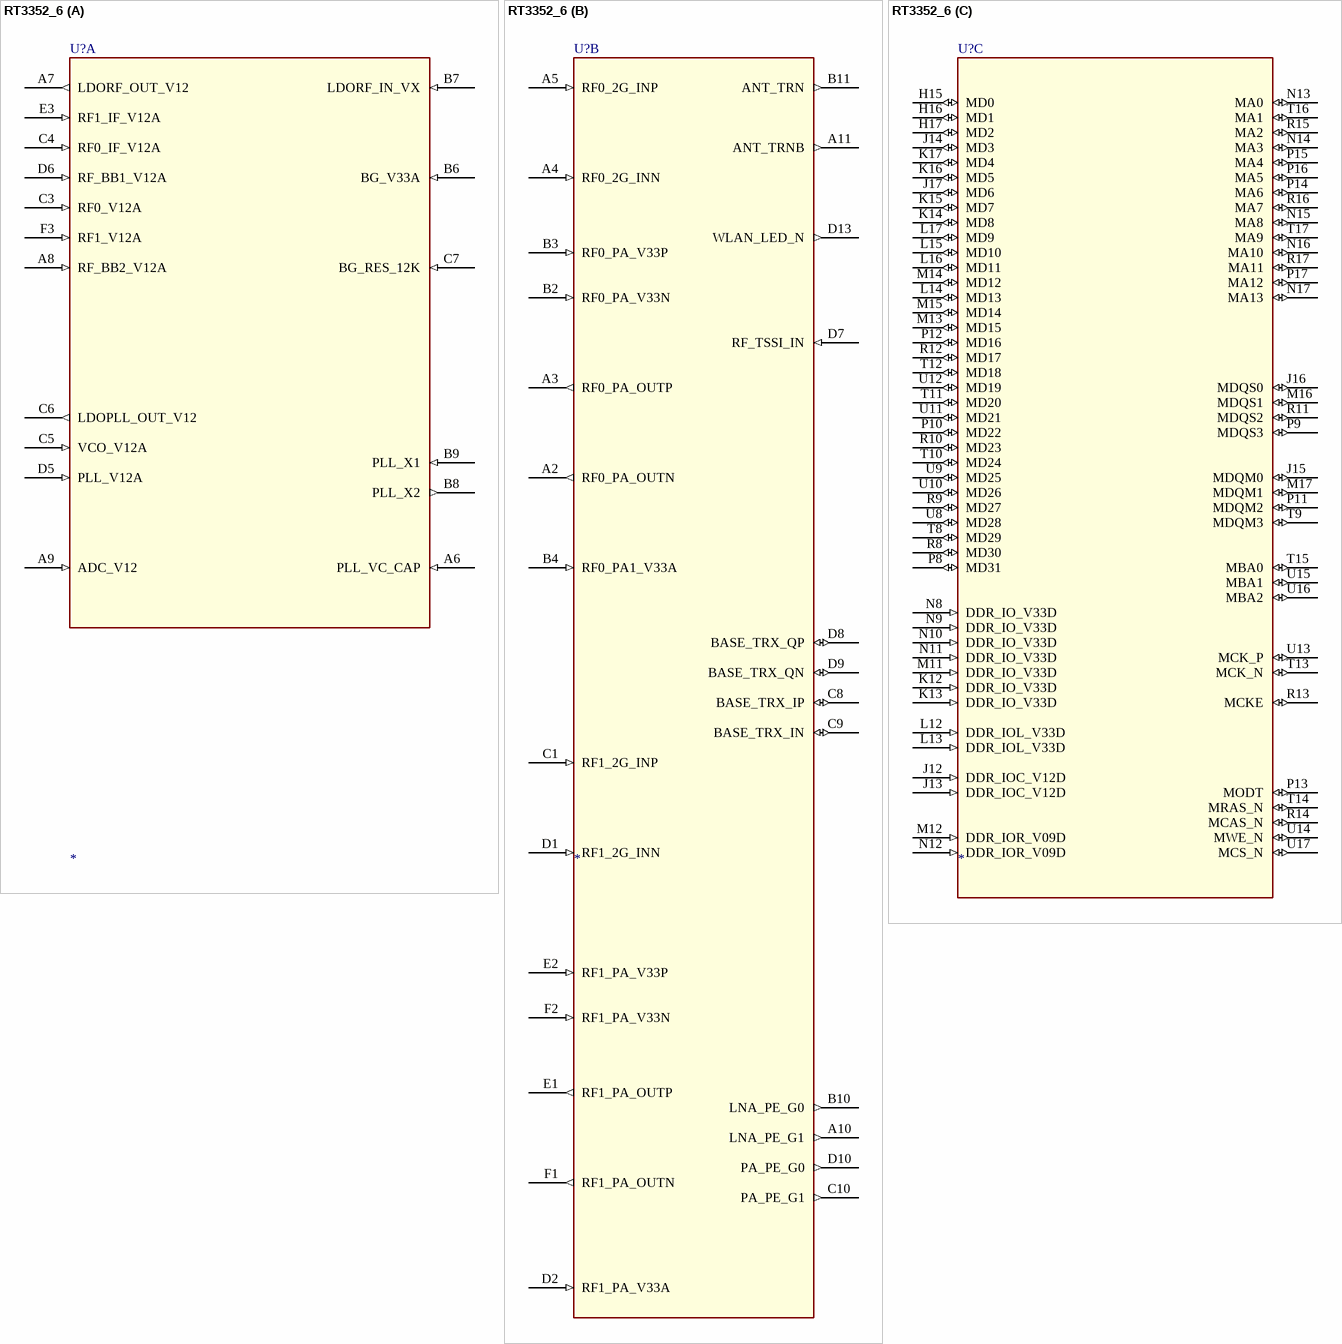
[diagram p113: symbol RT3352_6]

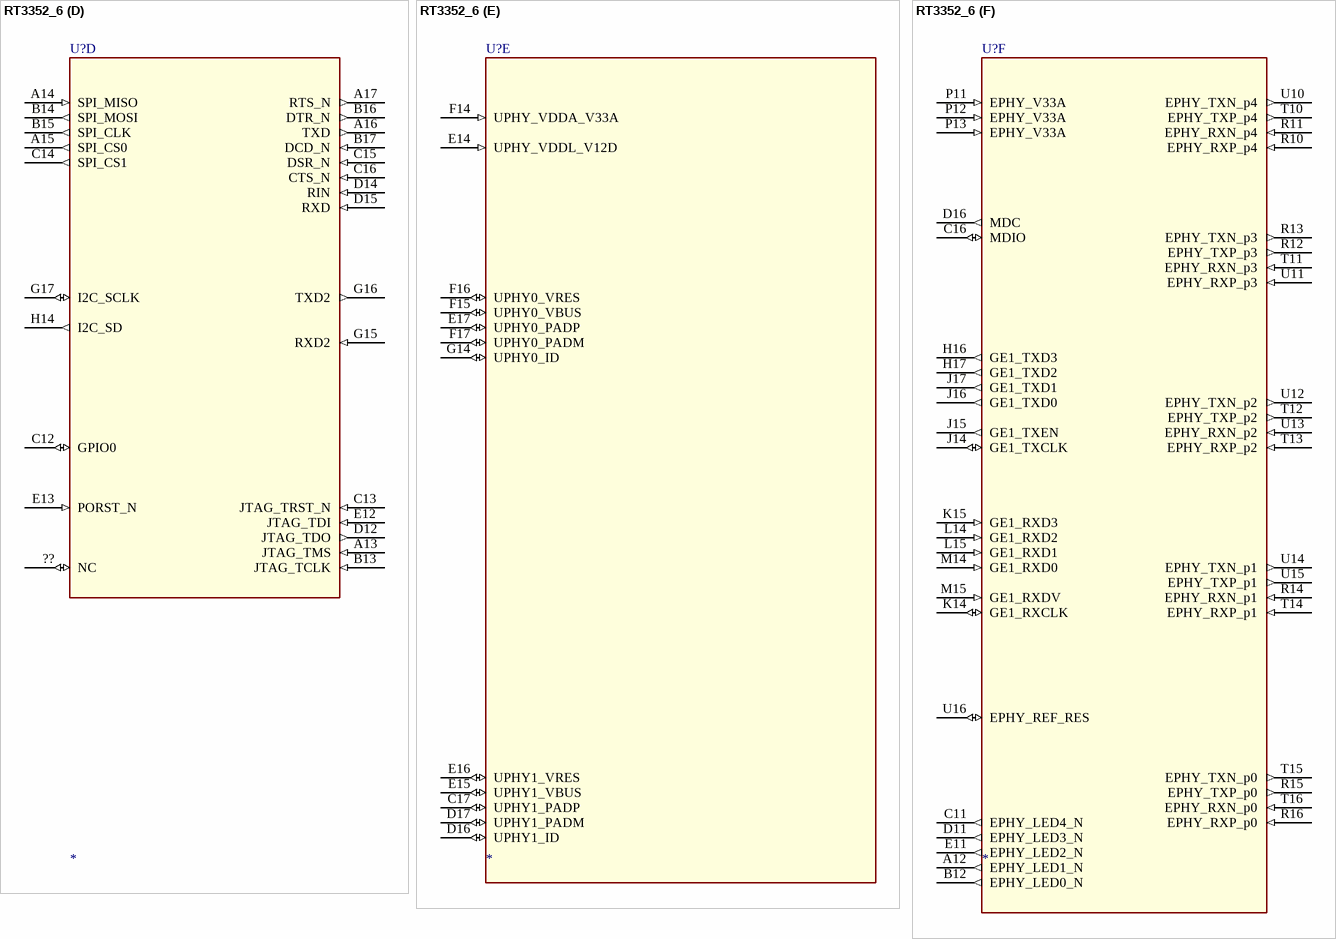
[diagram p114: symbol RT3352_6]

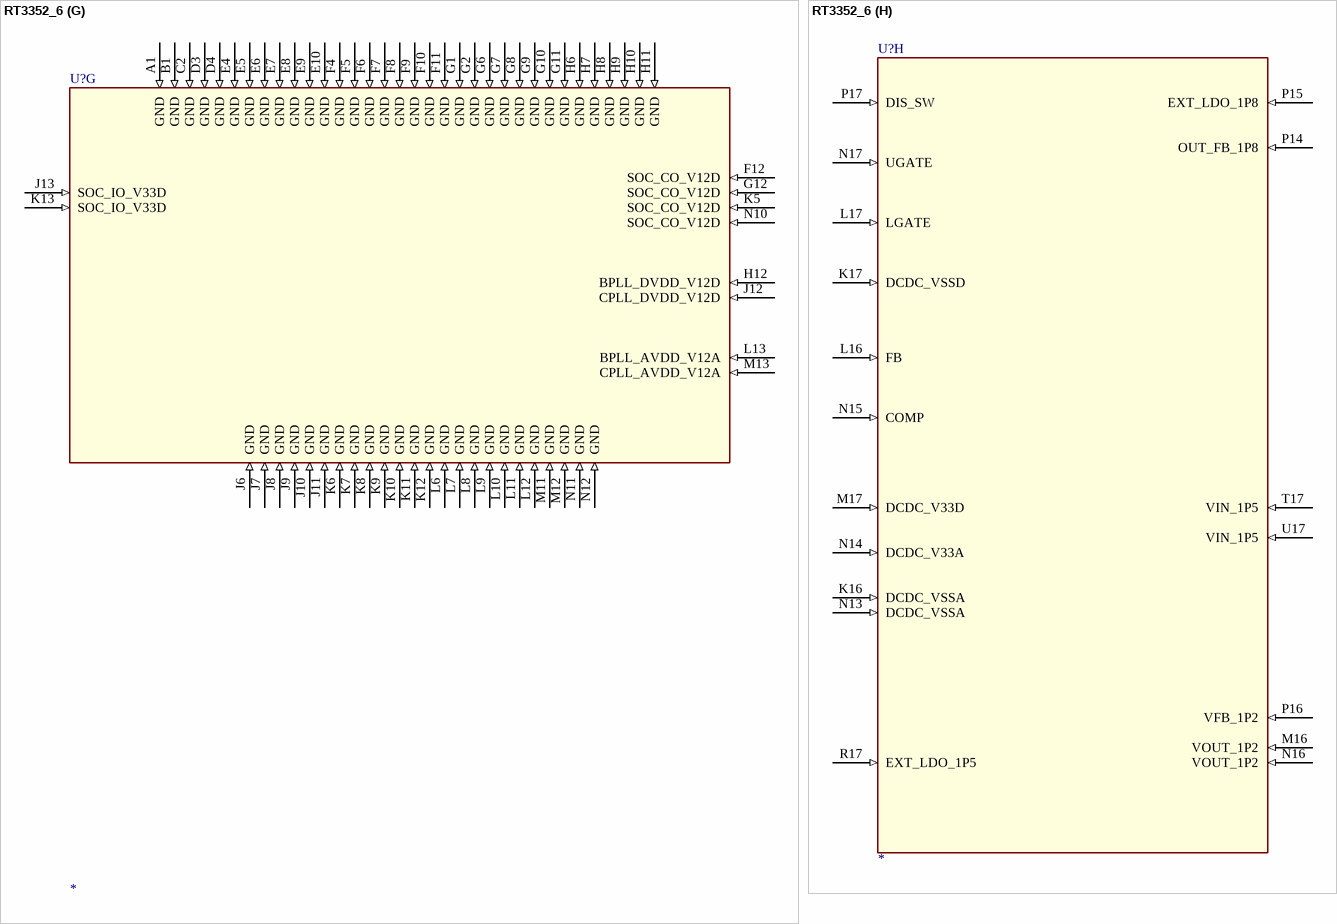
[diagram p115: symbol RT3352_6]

## RT3352_6
designator U?
part A pins: A6 PLL_VC_CAP (in), A7 LDORF_OUT_V12 (out), A8 RF_BB2_V12A (in), A9 ADC_V12 (in), B6 BG_V33A (in), B7 LDORF_IN_VX (in), B8 PLL_X2 (out), B9 PLL_X1 (in), C3 RF0_V12A (in), C4 RF0_IF_V12A (in), C5 VCO_V12A (in), C6 LDOPLL_OUT_V12 (out), C7 BG_RES_12K (in), D5 PLL_V12A (in), D6 RF_BB1_V12A (in), E3 RF1_IF_V12A (in), F3 RF1_V12A (in)
part B pins: A2 RF0_PA_OUTN (out), A3 RF0_PA_OUTP (out), A4 RF0_2G_INN (in), A5 RF0_2G_INP (in), A10 LNA_PE_G1 (out), A11 ANT_TRNB (out), B2 RF0_PA_V33N (in), B3 RF0_PA_V33P (in), B4 RF0_PA1_V33A (in), B10 LNA_PE_G0 (out), B11 ANT_TRN (out), C1 RF1_2G_INP (in), C8 BASE_TRX_IP (io), C9 BASE_TRX_IN (io), C10 PA_PE_G1 (out), D1 RF1_2G_INN (in), D2 RF1_PA_V33A (in), D7 RF_TSSI_IN (in), D8 BASE_TRX_QP (io), D9 BASE_TRX_QN (io), D10 PA_PE_G0 (out), D13 WLAN_LED_N (out), E1 RF1_PA_OUTP (out), E2 RF1_PA_V33P (in), F1 RF1_PA_OUTN (out), F2 RF1_PA_V33N (in)
part C pins: H15 MD0 (io), H16 MD1 (io), H17 MD2 (io), J12 DDR_IOC_V12D (in), J13 DDR_IOC_V12D (in), J14 MD3 (io), J15 MDQM0 (io), J16 MDQS0 (io), J17 MD6 (io), K12 DDR_IO_V33D (in), K13 DDR_IO_V33D (in), K14 MD8 (io), K15 MD7 (io), K16 MD5 (io), K17 MD4 (io), L12 DDR_IOL_V33D (in), L13 DDR_IOL_V33D (in), L14 MD13 (io), L15 MD10 (io), L16 MD11 (io), L17 MD9 (io), M11 DDR_IO_V33D (in), M12 DDR_IOR_V09D (in), M13 MD15 (io), M14 MD12 (io), M15 MD14 (io), M16 MDQS1 (io), M17 MDQM1 (io), N8 DDR_IO_V33D (in), N9 DDR_IO_V33D (in), N10 DDR_IO_V33D (in), N11 DDR_IO_V33D (in), N12 DDR_IOR_V09D (in), N13 MA0 (io), N14 MA3 (io), N15 MA8 (io), N16 MA10 (io), N17 MA13 (io), P8 MD31 (io), P9 MDQS3 (io), P10 MD22 (io), P11 MDQM2 (io), P12 MD16 (io), P13 MODT (io), P14 MA6 (io), P15 MA4 (io), P16 MA5 (io), P17 MA12 (io), R8 MD30 (io), R9 MD27 (io), R10 MD23 (io), R11 MDQS2 (io), R12 MD17 (io), R13 MCKE (io), R14 MCAS_N (io), R15 MA2 (io), R16 MA7 (io), R17 MA11 (io), T8 MD29 (io), T9 MDQM3 (io), T10 MD24 (io), T11 MD20 (io), T12 MD18 (io), T13 MCK_N (io), T14 MRAS_N (io), T15 MBA0 (io), T16 MA1 (io), T17 MA9 (io), U8 MD28 (io), U9 MD25 (io), U10 MD26 (io), U11 MD21 (io), U12 MD19 (io), U13 MCK_P (io), U14 MWE_N (io), U15 MBA1 (io), U16 MBA2 (io), U17 MCS_N (io)
part D pins: ?? NC (io), A13 JTAG_TMS (in), A14 SPI_MISO (in), A15 SPI_CS0 (out), A16 TXD (out), A17 RTS_N (out), B13 JTAG_TCLK (in), B14 SPI_MOSI (out), B15 SPI_CLK (out), B16 DTR_N (out), B17 DCD_N (in), C12 GPIO0 (io), C13 JTAG_TRST_N (in), C14 SPI_CS1 (out), C15 DSR_N (in), C16 CTS_N (in), D12 JTAG_TDO (out), D14 RIN (in), D15 RXD (in), E12 JTAG_TDI (in), E13 PORST_N (in), G15 RXD2 (in), G16 TXD2 (out), G17 I2C_SCLK (io), H14 I2C_SD (out)
part E pins: C17 UPHY1_PADP (io), D16 UPHY1_ID (io), D17 UPHY1_PADM (io), E14 UPHY_VDDL_V12D (in), E15 UPHY1_VBUS (io), E16 UPHY1_VRES (io), E17 UPHY0_PADP (io), F14 UPHY_VDDA_V33A (in), F15 UPHY0_VBUS (io), F16 UPHY0_VRES (io), F17 UPHY0_PADM (io), G14 UPHY0_ID (io)
part F pins: A12 EPHY_LED1_N (out), B12 EPHY_LED0_N (out), C11 EPHY_LED4_N (out), C16 MDIO (io), D11 EPHY_LED3_N (out), D16 MDC (out), E11 EPHY_LED2_N (out), H16 GE1_TXD3 (out), H17 GE1_TXD2 (out), J14 GE1_TXCLK (io), J15 GE1_TXEN (out), J16 GE1_TXD0 (out), J17 GE1_TXD1 (out), K14 GE1_RXCLK (io), K15 GE1_RXD3 (in), L14 GE1_RXD2 (in), L15 GE1_RXD1 (in), M14 GE1_RXD0 (in), M15 GE1_RXDV (in), P11 EPHY_V33A (in), P12 EPHY_V33A (in), P13 EPHY_V33A (in), R10 EPHY_RXP_p4 (in), R11 EPHY_RXN_p4 (in), R12 EPHY_TXP_p3 (out), R13 EPHY_TXN_p3 (out), R14 EPHY_RXN_p1 (in), R15 EPHY_TXP_p0 (out), R16 EPHY_RXP_p0 (in), T10 EPHY_TXP_p4 (out), T11 EPHY_RXN_p3 (in), T12 EPHY_TXP_p2 (out), T13 EPHY_RXP_p2 (in), T14 EPHY_RXP_p1 (in), T15 EPHY_TXN_p0 (out), T16 EPHY_RXN_p0 (in), U10 EPHY_TXN_p4 (out), U11 EPHY_RXP_p3 (in), U12 EPHY_TXN_p2 (out), U13 EPHY_RXN_p2 (in), U14 EPHY_TXN_p1 (out), U15 EPHY_TXP_p1 (out), U16 EPHY_REF_RES (io)
part G pins: A1 GND (in), B1 GND (in), C2 GND (in), D3 GND (in), D4 GND (in), E4 GND (in), E5 GND (in), E6 GND (in), E7 GND (in), E8 GND (in), E9 GND (in), E10 GND (in), F4 GND (in), F5 GND (in), F6 GND (in), F7 GND (in), F8 GND (in), F9 GND (in), F10 GND (in), F11 GND (in), F12 SOC_CO_V12D (in), G1 GND (in), G2 GND (in), G6 GND (in), G7 GND (in), G8 GND (in), G9 GND (in), G10 GND (in), G11 GND (in), G12 SOC_CO_V12D (in), H6 GND (in), H7 GND (in), H8 GND (in), H9 GND (in), H10 GND (in), H11 GND (in), H12 BPLL_DVDD_V12D (in), J6 GND (in), J7 GND (in), J8 GND (in), J9 GND (in), J10 GND (in), J11 GND (in), J12 CPLL_DVDD_V12D (in), J13 SOC_IO_V33D (in), K5 SOC_CO_V12D (in), K6 GND (in), K7 GND (in), K8 GND (in), K9 GND (in), K10 GND (in), K11 GND (in), K12 GND (in), K13 SOC_IO_V33D (in), L6 GND (in), L7 GND (in), L8 GND (in), L9 GND (in), L10 GND (in), L11 GND (in), L12 GND (in), L13 BPLL_AVDD_V12A (in), M11 GND (in), M12 GND (in), M13 CPLL_AVDD_V12A (in), N10 SOC_CO_V12D (in), N11 GND (in), N12 GND (in)
part H pins: K16 DCDC_VSSA (in), K17 DCDC_VSSD (in), L16 FB (in), L17 LGATE (in), M16 VOUT_1P2 (in), M17 DCDC_V33D (in), N13 DCDC_VSSA (in), N14 DCDC_V33A (in), N15 COMP (in), N16 VOUT_1P2 (in), N17 UGATE (in), P14 OUT_FB_1P8 (in), P15 EXT_LDO_1P8 (in), P16 VFB_1P2 (in), P17 DIS_SW (in), R17 EXT_LDO_1P5 (in), T17 VIN_1P5 (in), U17 VIN_1P5 (in)

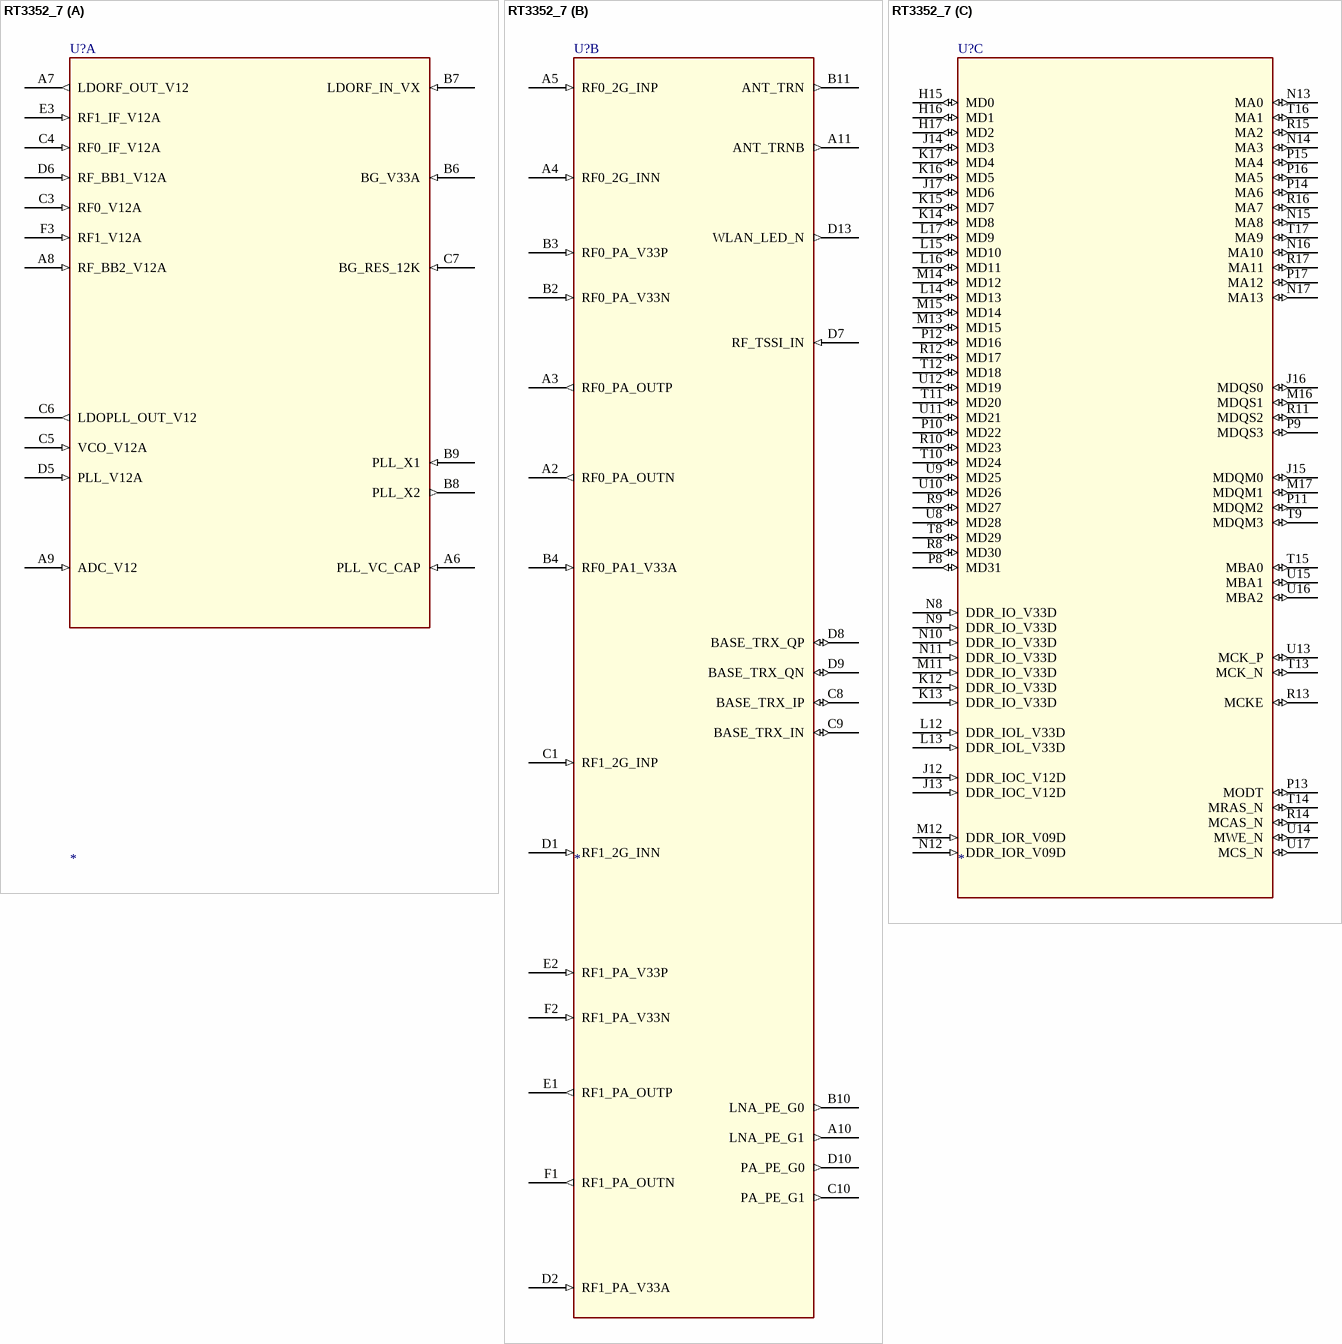
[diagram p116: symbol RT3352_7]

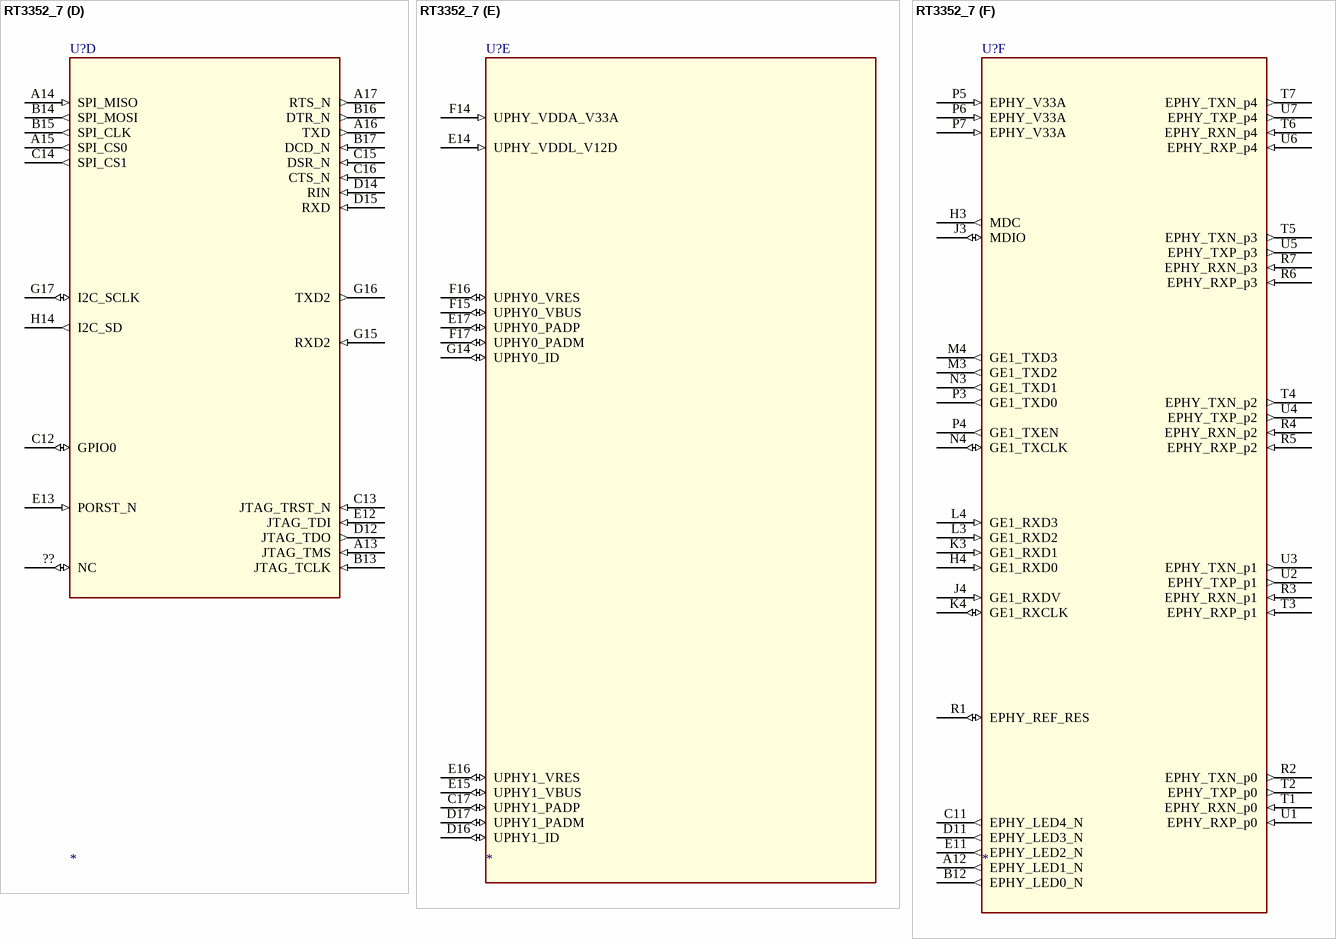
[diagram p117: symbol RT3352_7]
